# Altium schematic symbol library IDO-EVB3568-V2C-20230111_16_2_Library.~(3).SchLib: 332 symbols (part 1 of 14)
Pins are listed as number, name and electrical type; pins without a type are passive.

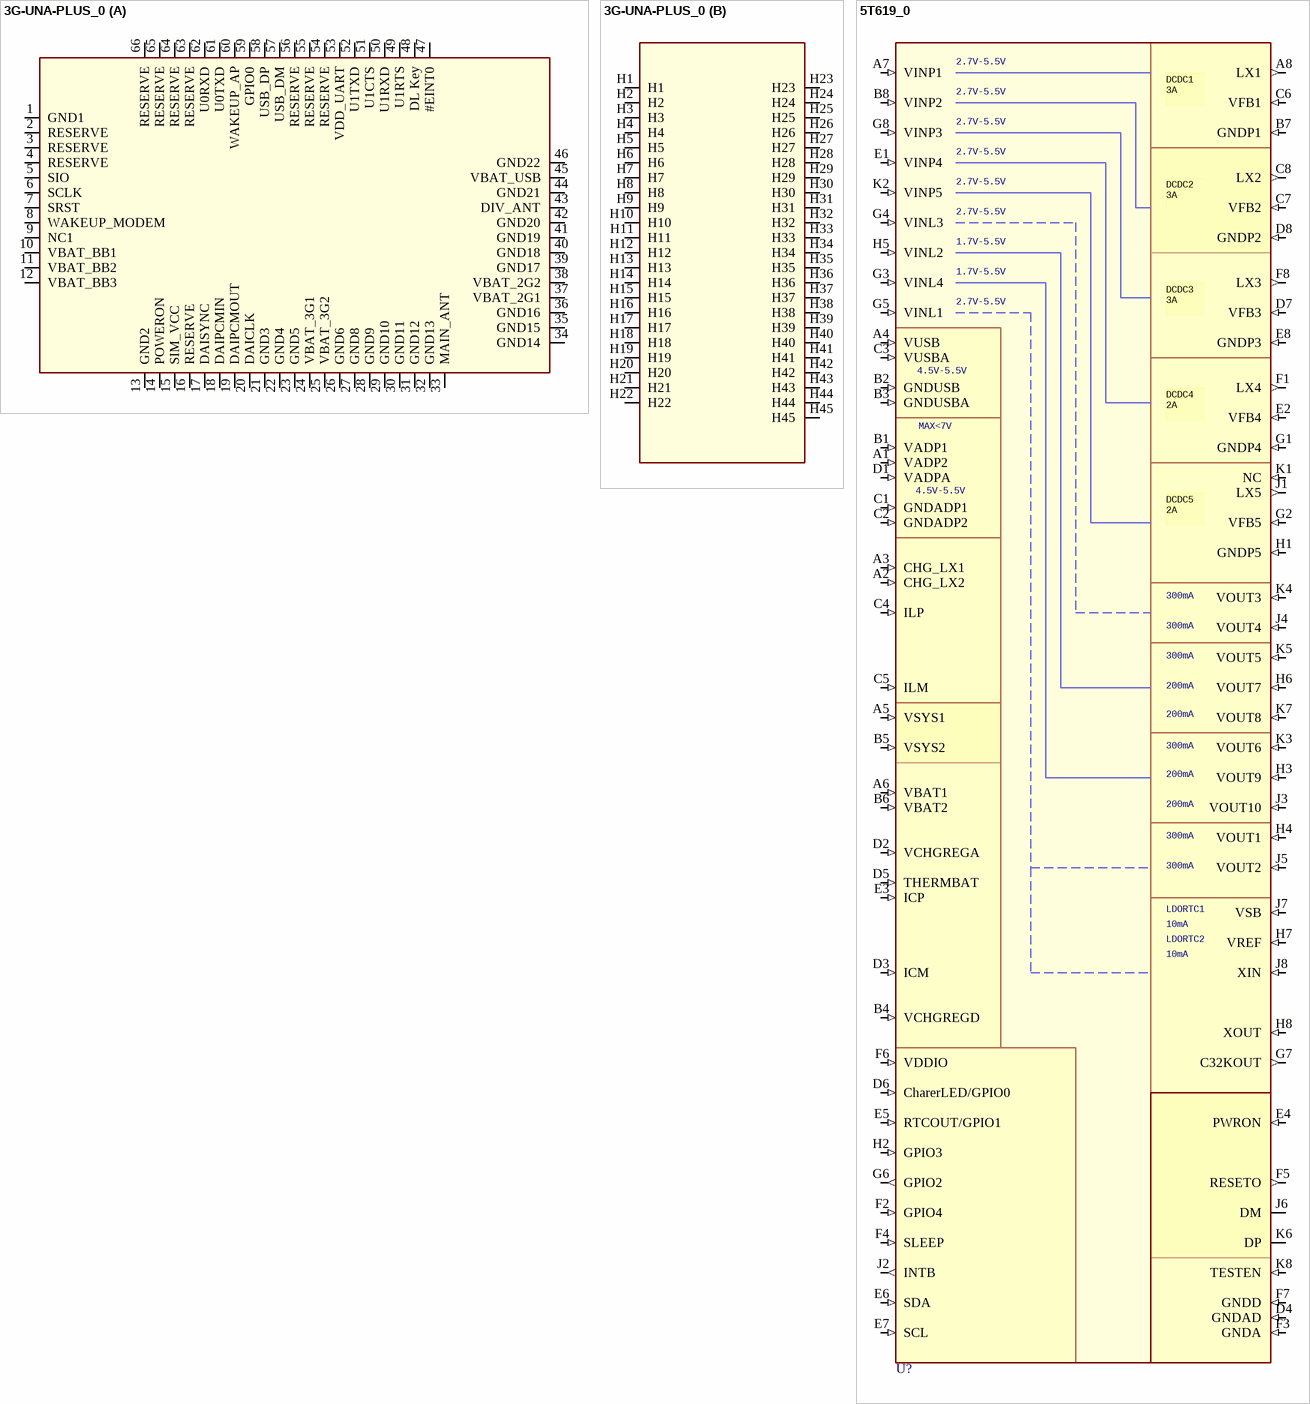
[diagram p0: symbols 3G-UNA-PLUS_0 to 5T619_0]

## 3G-UNA-PLUS_0
designator U?
Altium-Right: 340; Altium-Bottom: 210; Altium-Right1: 110; Altium-Bottom1: 280
part A pins: 1 GND1, 2 RESERVE, 3 RESERVE, 4 RESERVE, 5 SIO, 6 SCLK, 7 SRST, 8 WAKEUP_MODEM, 9 NC1, 10 VBAT_BB1, 11 VBAT_BB2, 12 VBAT_BB3, 13 GND2, 14 POWERON, 15 SIM_VCC, 16 RESERVE, 17 DAISYNC, 18 DAIPCMIN, 19 DAIPCMOUT, 20 DAICLK, 21 GND3, 22 GND4, 23 GND5, 24 VBAT_3G1, 25 VBAT_3G2, 26 GND6, 27 GND8, 28 GND9, 29 GND10, 30 GND11, 31 GND12, 32 GND13, 33 MAIN_ANT, 34 GND14, 35 GND15, 36 GND16, 37 VBAT_2G1, 38 VBAT_2G2, 39 GND17, 40 GND18, 41 GND19, 42 GND20, 43 DIV_ANT, 44 GND21, 45 VBAT_USB, 46 GND22, 47 #EINT0, 48 DL Key, 49 U1RTS, 50 U1RXD, 51 U1CTS, 52 U1TXD, 53 VDD_UART, 54 RESERVE, 55 RESERVE, 56 RESERVE, 57 USB_DM, 58 USB_DP, 59 GPIO0, 60 WAKEUP_AP, 61 U0TXD, 62 U0RXD, 63 RESERVE, 64 RESERVE, 65 RESERVE, 66 RESERVE
part B pins: H1, H2, H3, H4, H5, H6, H7, H8, H9, H10, H11, H12, H13, H14, H15, H16, H17, H18, H19, H20, H21, H22, H23, H24, H25, H26, H27, H28, H29, H30, H31, H32, H33, H34, H35, H36, H37, H38, H39, H40, H41, H42, H43, H44, H45

## 5T619_0
designator U?  (value not drawn)
Altium-Right: 250; Altium-Bottom: 880
pins: A1 VADP2 (in), A2 CHG_LX2 (in), A3 CHG_LX1 (in), A4 VUSB (in), A5 VSYS1 (in), A6 VBAT1 (in), A7 VINP1 (in), A8 LX1 (out), B1 VADP1 (in), B2 GNDUSB (in), B3 GNDUSBA (in), B4 VCHGREGD (in), B5 VSYS2 (in), B6 VBAT2 (in), B7 GNDP1 (in), B8 VINP2 (in), C1 GNDADP1 (in), C2 GNDADP2 (in), C3 VUSBA (in), C4 ILP (in), C5 ILM (in), C6 VFB1 (in), C7 VFB2 (in), C8 LX2 (out), D1 VADPA (in), D2 VCHGREGA (in), D3 ICM (in), D4 GNDAD (in), D5 THERMBAT (in), D6 CharerLED/GPIO0 (in), D7 VFB3 (in), D8 GNDP2 (in), E1 VINP4 (in), E2 VFB4 (in), E3 ICP (in), E4 PWRON (in), E5 RTCOUT/GPIO1 (in), E6 SDA (in), E7 SCL (in), E8 GNDP3 (in), F1 LX4 (out), F2 GPIO4 (in), F3 GNDA (in), F4 SLEEP (in), F5 RESETO (out), F6 VDDIO (in), F7 GNDD (in), F8 LX3 (out), G1 GNDP4 (in), G2 VFB5 (in), G3 VINL4 (in), G4 VINL3 (in), G5 VINL1 (in), G6 GPIO2 (out), G7 C32KOUT (out), G8 VINP3 (in), H1 GNDP5 (in), H2 GPIO3 (in), H3 VOUT9 (in), H4 VOUT1 (in), H5 VINL2 (in), H6 VOUT7 (in), H7 VREF (in), H8 XOUT (in), J1 LX5 (out), J2 INTB (out), J3 VOUT10 (in), J4 VOUT4 (in), J5 VOUT2 (in), J6 DM, J7 VSB (in), J8 XIN (in), K1 NC (in), K2 VINP5 (in), K3 VOUT6 (in), K4 VOUT3 (in), K5 VOUT5 (in), K6 DP, K7 VOUT8 (in), K8 TESTEN (in)

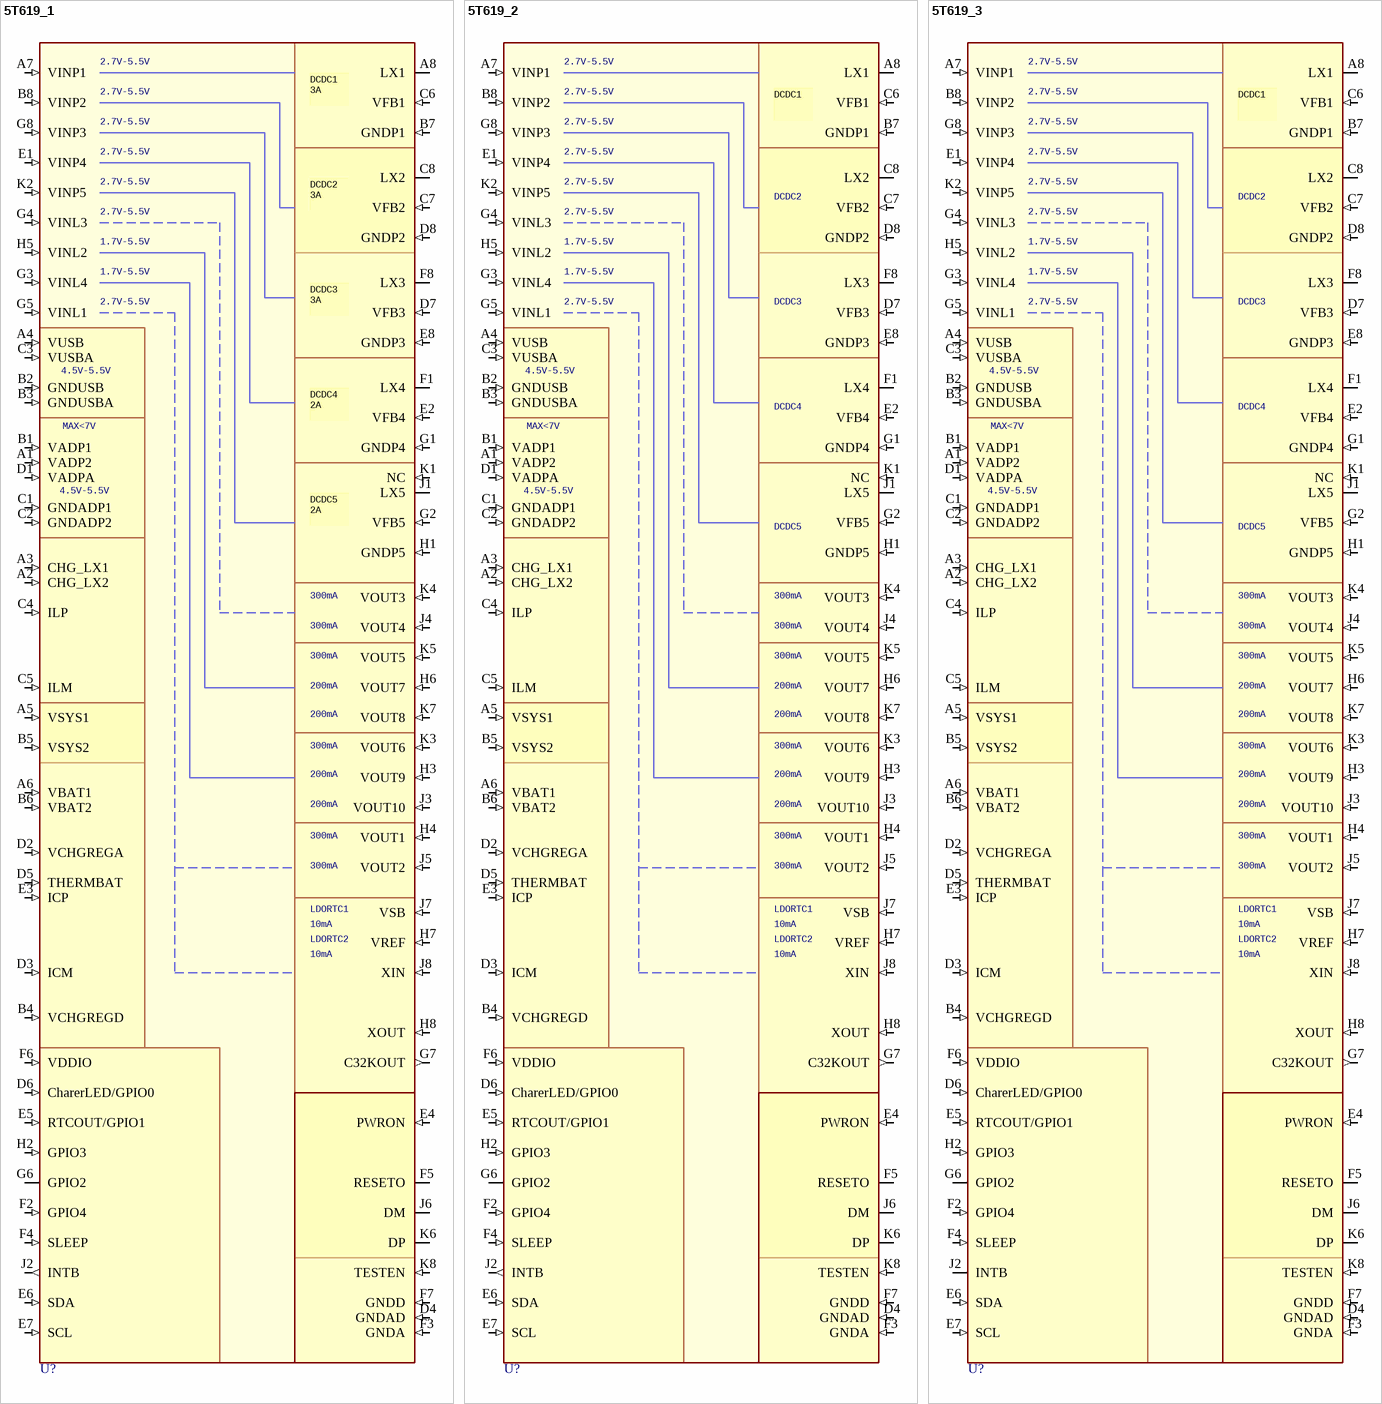
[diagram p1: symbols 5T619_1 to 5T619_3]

## 5T619_1
designator U?  (value not drawn)
Altium-Right: 250; Altium-Bottom: 880
pins: A1 VADP2 (in), A2 CHG_LX2 (in), A3 CHG_LX1 (in), A4 VUSB (in), A5 VSYS1 (in), A6 VBAT1 (in), A7 VINP1 (in), A8 LX1, B1 VADP1 (in), B2 GNDUSB (in), B3 GNDUSBA (in), B4 VCHGREGD (in), B5 VSYS2 (in), B6 VBAT2 (in), B7 GNDP1 (in), B8 VINP2 (in), C1 GNDADP1 (in), C2 GNDADP2 (in), C3 VUSBA (in), C4 ILP (in), C5 ILM (in), C6 VFB1 (in), C7 VFB2 (in), C8 LX2, D1 VADPA (in), D2 VCHGREGA (in), D3 ICM (in), D4 GNDAD (in), D5 THERMBAT (in), D6 CharerLED/GPIO0 (in), D7 VFB3 (in), D8 GNDP2 (in), E1 VINP4 (in), E2 VFB4 (in), E3 ICP (in), E4 PWRON (in), E5 RTCOUT/GPIO1 (in), E6 SDA (in), E7 SCL (in), E8 GNDP3 (in), F1 LX4, F2 GPIO4 (in), F3 GNDA (in), F4 SLEEP (in), F5 RESETO, F6 VDDIO (in), F7 GNDD (in), F8 LX3, G1 GNDP4 (in), G2 VFB5 (in), G3 VINL4 (in), G4 VINL3 (in), G5 VINL1 (in), G6 GPIO2, G7 C32KOUT (out), G8 VINP3 (in), H1 GNDP5 (in), H2 GPIO3 (in), H3 VOUT9 (in), H4 VOUT1 (in), H5 VINL2 (in), H6 VOUT7 (in), H7 VREF (in), H8 XOUT (in), J1 LX5, J2 INTB (out), J3 VOUT10 (in), J4 VOUT4 (in), J5 VOUT2 (in), J6 DM, J7 VSB (in), J8 XIN (in), K1 NC (in), K2 VINP5 (in), K3 VOUT6 (in), K4 VOUT3 (in), K5 VOUT5 (in), K6 DP, K7 VOUT8 (in), K8 TESTEN (in)

## 5T619_2
designator U?  (value not drawn)
Altium-Right: 250; Altium-Bottom: 880
pins: A1 VADP2 (in), A2 CHG_LX2 (in), A3 CHG_LX1 (in), A4 VUSB (in), A5 VSYS1 (in), A6 VBAT1 (in), A7 VINP1 (in), A8 LX1, B1 VADP1 (in), B2 GNDUSB (in), B3 GNDUSBA (in), B4 VCHGREGD (in), B5 VSYS2 (in), B6 VBAT2 (in), B7 GNDP1 (in), B8 VINP2 (in), C1 GNDADP1 (in), C2 GNDADP2 (in), C3 VUSBA (in), C4 ILP (in), C5 ILM (in), C6 VFB1 (in), C7 VFB2 (in), C8 LX2, D1 VADPA (in), D2 VCHGREGA (in), D3 ICM (in), D4 GNDAD (in), D5 THERMBAT (in), D6 CharerLED/GPIO0 (in), D7 VFB3 (in), D8 GNDP2 (in), E1 VINP4 (in), E2 VFB4 (in), E3 ICP (in), E4 PWRON (in), E5 RTCOUT/GPIO1 (in), E6 SDA (in), E7 SCL (in), E8 GNDP3 (in), F1 LX4, F2 GPIO4 (in), F3 GNDA (in), F4 SLEEP (in), F5 RESETO, F6 VDDIO (in), F7 GNDD (in), F8 LX3, G1 GNDP4 (in), G2 VFB5 (in), G3 VINL4 (in), G4 VINL3 (in), G5 VINL1 (in), G6 GPIO2, G7 C32KOUT (out), G8 VINP3 (in), H1 GNDP5 (in), H2 GPIO3 (in), H3 VOUT9 (in), H4 VOUT1 (in), H5 VINL2 (in), H6 VOUT7 (in), H7 VREF (in), H8 XOUT (in), J1 LX5, J2 INTB (out), J3 VOUT10 (in), J4 VOUT4 (in), J5 VOUT2 (in), J6 DM, J7 VSB (in), J8 XIN (in), K1 NC (in), K2 VINP5 (in), K3 VOUT6 (in), K4 VOUT3 (in), K5 VOUT5 (in), K6 DP, K7 VOUT8 (in), K8 TESTEN (in)

## 5T619_3
designator U?  (value not drawn)
Altium-Right: 250; Altium-Bottom: 880
pins: A1 VADP2 (in), A2 CHG_LX2 (in), A3 CHG_LX1 (in), A4 VUSB (in), A5 VSYS1 (in), A6 VBAT1 (in), A7 VINP1 (in), A8 LX1, B1 VADP1 (in), B2 GNDUSB (in), B3 GNDUSBA (in), B4 VCHGREGD (in), B5 VSYS2 (in), B6 VBAT2 (in), B7 GNDP1 (in), B8 VINP2 (in), C1 GNDADP1 (in), C2 GNDADP2 (in), C3 VUSBA (in), C4 ILP (in), C5 ILM (in), C6 VFB1 (in), C7 VFB2 (in), C8 LX2, D1 VADPA (in), D2 VCHGREGA (in), D3 ICM (in), D4 GNDAD (in), D5 THERMBAT (in), D6 CharerLED/GPIO0 (in), D7 VFB3 (in), D8 GNDP2 (in), E1 VINP4 (in), E2 VFB4 (in), E3 ICP (in), E4 PWRON (in), E5 RTCOUT/GPIO1 (in), E6 SDA (in), E7 SCL (in), E8 GNDP3 (in), F1 LX4, F2 GPIO4 (in), F3 GNDA (in), F4 SLEEP (in), F5 RESETO, F6 VDDIO (in), F7 GNDD (in), F8 LX3, G1 GNDP4 (in), G2 VFB5 (in), G3 VINL4 (in), G4 VINL3 (in), G5 VINL1 (in), G6 GPIO2, G7 C32KOUT (out), G8 VINP3 (in), H1 GNDP5 (in), H2 GPIO3 (in), H3 VOUT9 (in), H4 VOUT1 (in), H5 VINL2 (in), H6 VOUT7 (in), H7 VREF (in), H8 XOUT (in), J1 LX5, J2 INTB, J3 VOUT10 (in), J4 VOUT4 (in), J5 VOUT2 (in), J6 DM, J7 VSB (in), J8 XIN (in), K1 NC (in), K2 VINP5 (in), K3 VOUT6 (in), K4 VOUT3 (in), K5 VOUT5 (in), K6 DP, K7 VOUT8 (in), K8 TESTEN (in)

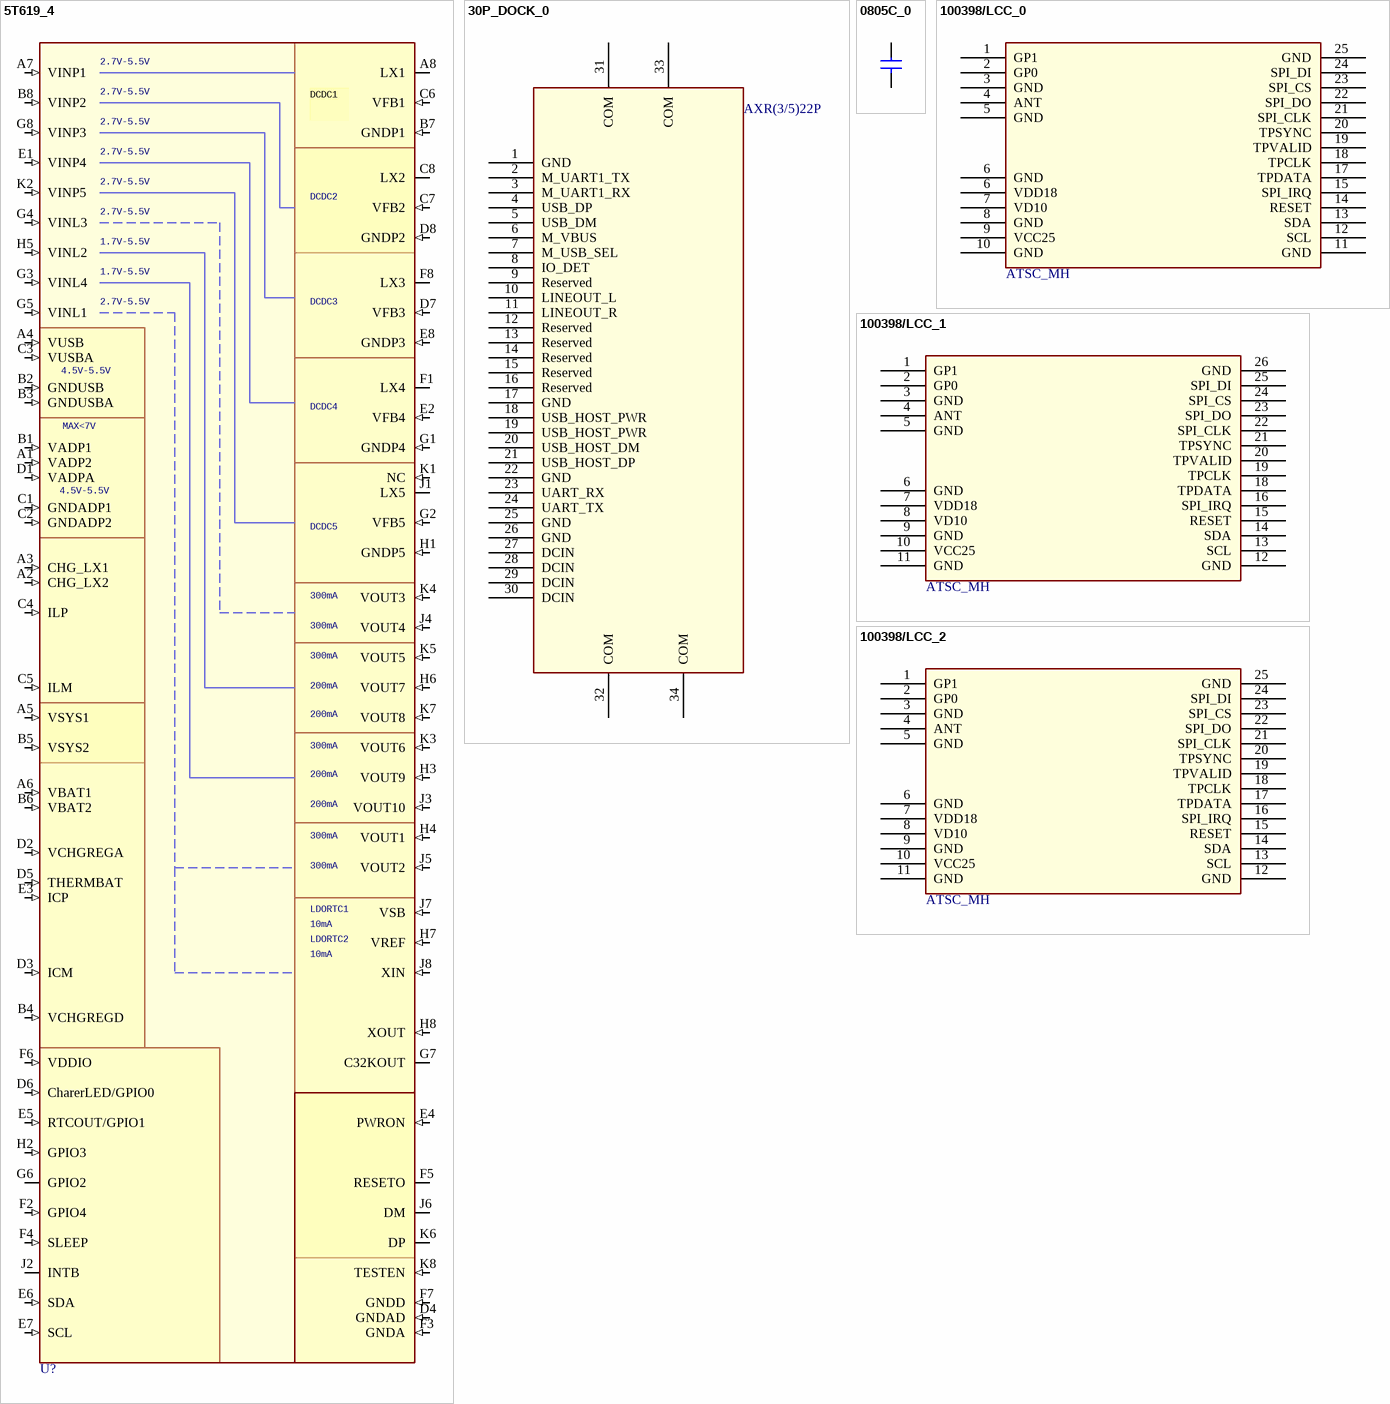
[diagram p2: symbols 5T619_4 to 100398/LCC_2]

## 5T619_4
designator U?  (value not drawn)
Altium-Right: 250; Altium-Bottom: 880
pins: A1 VADP2 (in), A2 CHG_LX2 (in), A3 CHG_LX1 (in), A4 VUSB (in), A5 VSYS1 (in), A6 VBAT1 (in), A7 VINP1 (in), A8 LX1, B1 VADP1 (in), B2 GNDUSB (in), B3 GNDUSBA (in), B4 VCHGREGD (in), B5 VSYS2 (in), B6 VBAT2 (in), B7 GNDP1 (in), B8 VINP2 (in), C1 GNDADP1 (in), C2 GNDADP2 (in), C3 VUSBA (in), C4 ILP (in), C5 ILM (in), C6 VFB1 (in), C7 VFB2 (in), C8 LX2, D1 VADPA (in), D2 VCHGREGA (in), D3 ICM (in), D4 GNDAD (in), D5 THERMBAT (in), D6 CharerLED/GPIO0 (in), D7 VFB3 (in), D8 GNDP2 (in), E1 VINP4 (in), E2 VFB4 (in), E3 ICP (in), E4 PWRON (in), E5 RTCOUT/GPIO1 (in), E6 SDA (in), E7 SCL (in), E8 GNDP3 (in), F1 LX4, F2 GPIO4 (in), F3 GNDA (in), F4 SLEEP (in), F5 RESETO, F6 VDDIO (in), F7 GNDD (in), F8 LX3, G1 GNDP4 (in), G2 VFB5 (in), G3 VINL4 (in), G4 VINL3 (in), G5 VINL1 (in), G6 GPIO2, G7 C32KOUT, G8 VINP3 (in), H1 GNDP5 (in), H2 GPIO3 (in), H3 VOUT9 (in), H4 VOUT1 (in), H5 VINL2 (in), H6 VOUT7 (in), H7 VREF (in), H8 XOUT (in), J1 LX5, J2 INTB, J3 VOUT10 (in), J4 VOUT4 (in), J5 VOUT2 (in), J6 DM, J7 VSB (in), J8 XIN (in), K1 NC (in), K2 VINP5 (in), K3 VOUT6 (in), K4 VOUT3 (in), K5 VOUT5 (in), K6 DP, K7 VOUT8 (in), K8 TESTEN (in)

## 30P_DOCK_0
designator CON?, comment AXR(3/5)22P
Altium-Right: 140; Altium-Bottom: 390
footprint 30P_DOCK_1
pins: 1 GND, 2 M_UART1_TX, 3 M_UART1_RX, 4 USB_DP, 5 USB_DM, 6 M_VBUS, 7 M_USB_SEL, 8 IO_DET, 9 Reserved, 10 LINEOUT_L, 11 LINEOUT_R, 12 Reserved, 13 Reserved, 14 Reserved, 15 Reserved, 16 Reserved, 17 GND, 18 USB_HOST_PWR, 19 USB_HOST_PWR, 20 USB_HOST_DM, 21 USB_HOST_DP, 22 GND, 23 UART_RX, 24 UART_TX, 25 GND, 26 GND, 27 DCIN, 28 DCIN, 29 DCIN, 30 DCIN, 31 COM, 32 COM, 33 COM, 34 COM

## 0805C_0
designator C?
Altium-Right: 20; Altium-Bottom: 10
footprint 0805C
pins: 1, 2

## 100398/LCC_0
designator U?, comment ATSC_MH
Altium-Right: 210; Altium-Bottom: 150
pins: 1 GP1, 2 GP0, 3 GND, 4 ANT, 5 GND, 6 VDD18, 6 GND, 7 VD10, 8 GND, 9 VCC25, 10 GND, 11 GND, 12 SCL, 13 SDA, 14 RESET, 15 SPI_IRQ, 17 TPDATA, 18 TPCLK, 19 TPVALID, 20 TPSYNC, 21 SPI_CLK, 22 SPI_DO, 23 SPI_CS, 24 SPI_DI, 25 GND

## 100398/LCC_1
designator U?, comment ATSC_MH
Altium-Right: 210; Altium-Bottom: 150
pins: 1 GP1, 2 GP0, 3 GND, 4 ANT, 5 GND, 6 GND, 7 VDD18, 8 VD10, 9 GND, 10 VCC25, 11 GND, 12 GND, 13 SCL, 14 SDA, 15 RESET, 16 SPI_IRQ, 18 TPDATA, 19 TPCLK, 20 TPVALID, 21 TPSYNC, 22 SPI_CLK, 23 SPI_DO, 24 SPI_CS, 25 SPI_DI, 26 GND

## 100398/LCC_2
designator U?, comment ATSC_MH
Altium-Right: 210; Altium-Bottom: 150
pins: 1 GP1, 2 GP0, 3 GND, 4 ANT, 5 GND, 6 GND, 7 VDD18, 8 VD10, 9 GND, 10 VCC25, 11 GND, 12 GND, 13 SCL, 14 SDA, 15 RESET, 16 SPI_IRQ, 17 TPDATA, 18 TPCLK, 19 TPVALID, 20 TPSYNC, 21 SPI_CLK, 22 SPI_DO, 23 SPI_CS, 24 SPI_DI, 25 GND

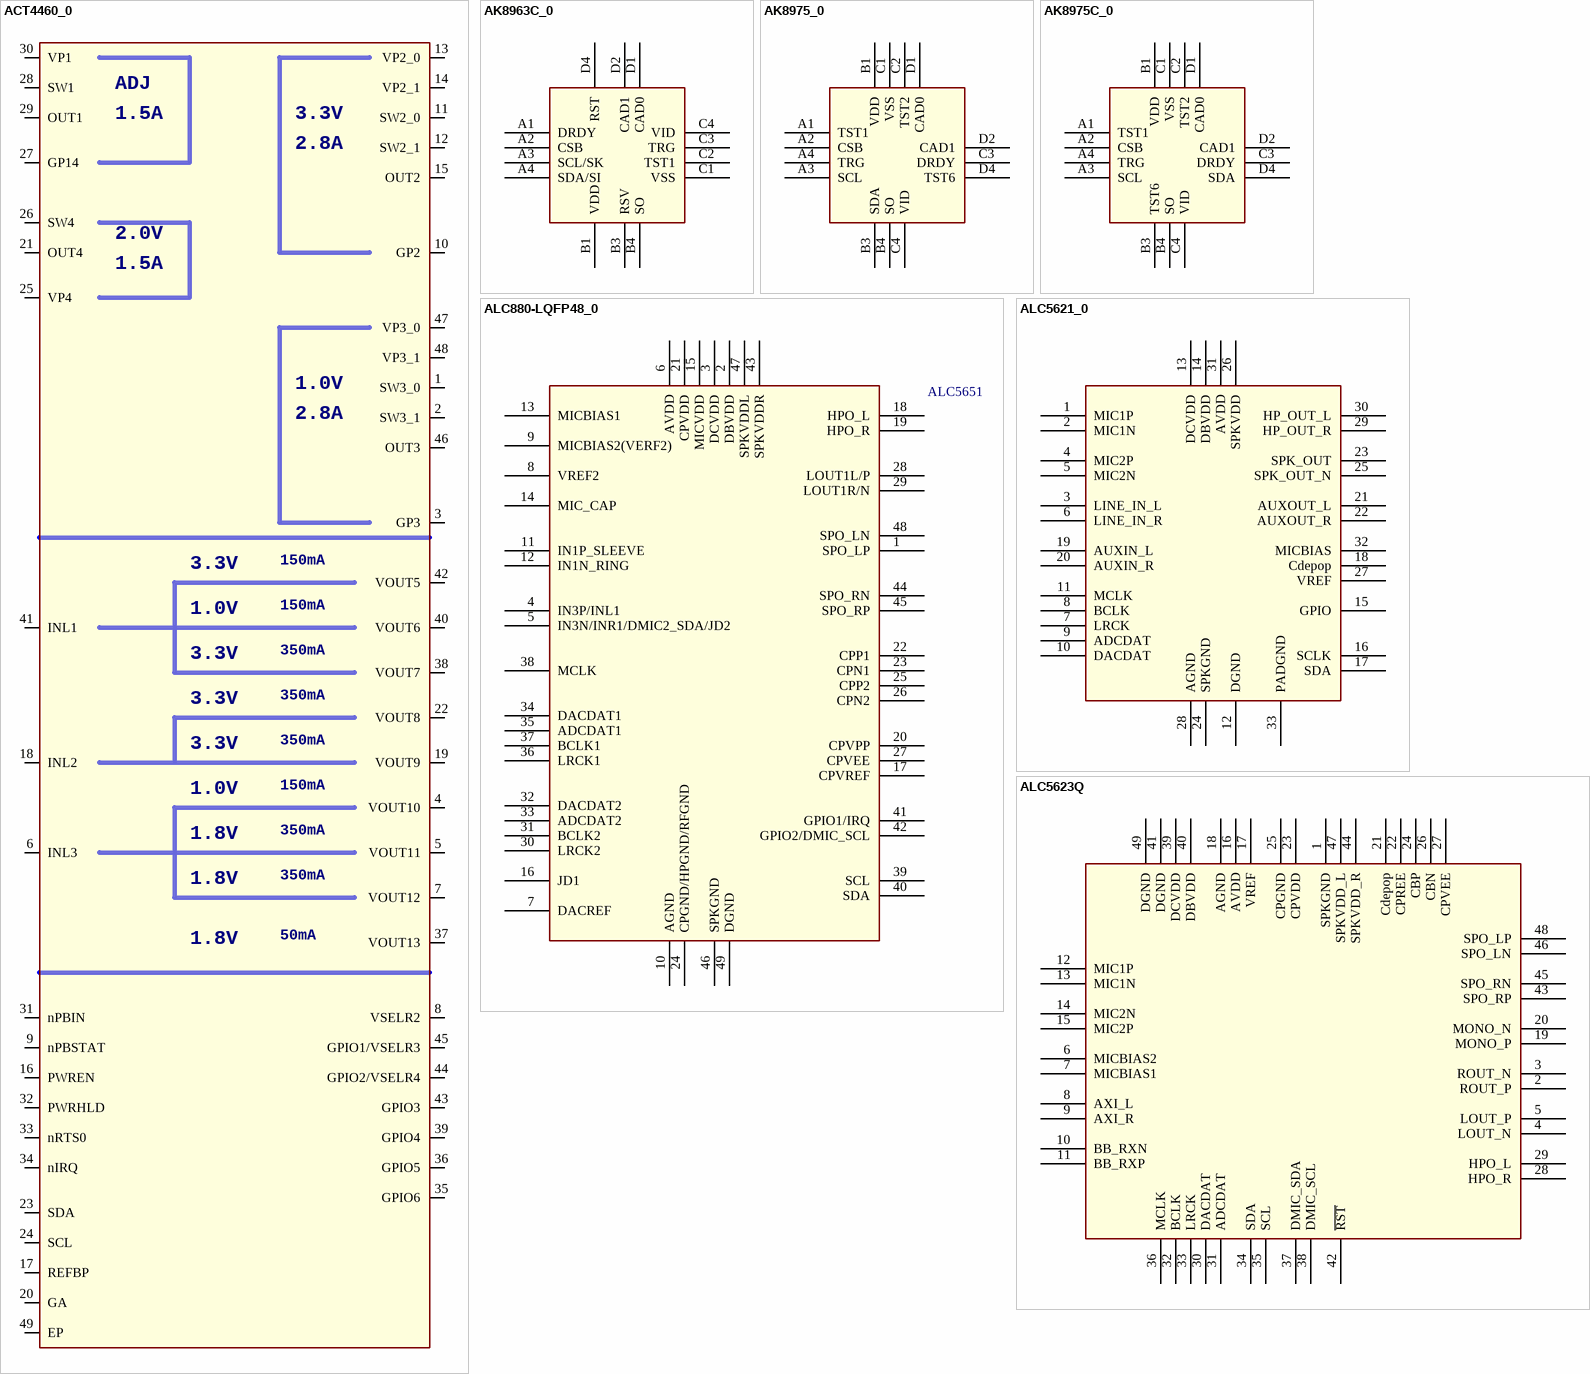
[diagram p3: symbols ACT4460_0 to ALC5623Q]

## ACT4460_0
designator U?
Altium-Right: 260; Altium-Bottom: 870
pins: 1 SW3_0, 2 SW3_1, 3 GP3, 4 VOUT10, 5 VOUT11, 6 INL3, 7 VOUT12, 8 VSELR2, 9 nPBSTAT, 10 GP2, 11 SW2_0, 12 SW2_1, 13 VP2_0, 14 VP2_1, 15 OUT2, 16 PWREN, 17 REFBP, 18 INL2, 19 VOUT9, 20 GA, 21 OUT4, 22 VOUT8, 23 SDA, 24 SCL, 25 VP4, 26 SW4, 27 GP14, 28 SW1, 29 OUT1, 30 VP1, 31 nPBIN, 32 PWRHLD, 33 nRTS0, 34 nIRQ, 35 GPIO6, 36 GPIO5, 37 VOUT13, 38 VOUT7, 39 GPIO4, 40 VOUT6, 41 INL1, 42 VOUT5, 43 GPIO3, 44 GPIO2/VSELR4, 45 GPIO1/VSELR3, 46 OUT3, 47 VP3_0, 48 VP3_1, 49 EP

## AK8963C_0
designator U?
Altium-Right: 90
footprint AK8975B
pins: A1 DRDY, A2 CSB, A3 SCL/SK, A4 SDA/SI, B1 VDD, B3 RSV, B4 SO, C1 VSS, C2 TST1, C3 TRG, C4 VID, D1 CAD0, D2 CAD1, D4 RST

## AK8975_0
designator U?
Altium-Right: 90
footprint QFN16-4X4
pins: A1 TST1, A2 CSB, A3 SCL, A4 TRG, B1 VDD, B3 SDA, B4 SO, C1 VSS, C2 TST2, C3 DRDY, C4 VID, D1 CAD0, D2 CAD1, D4 TST6

## AK8975C_0
designator U?
Altium-Right: 90
footprint AK8975B
pins: A1 TST1, A2 CSB, A3 SCL, A4 TRG, B1 VDD, B3 TST6, B4 SO, C1 VSS, C2 TST2, C3 DRDY, C4 VID, D1 CAD0, D2 CAD1, D4 SDA

## ALC880-LQFP48_0
designator U?, comment ALC5651
Altium-Right: 220; Altium-Bottom: 370
pins: 1 SPO_LP, 2 DBVDD, 3 DCVDD, 4 IN3P/INL1, 5 IN3N/INR1/DMIC2_SDA/JD2, 6 AVDD, 7 DACREF, 8 VREF2, 9 MICBIAS2(VERF2), 10 AGND, 11 IN1P_SLEEVE, 12 IN1N_RING, 13 MICBIAS1, 14 MIC_CAP, 15 MICVDD, 16 JD1, 17 CPVREF, 18 HPO_L, 19 HPO_R, 20 CPVPP, 21 CPVDD, 22 CPP1, 23 CPN1, 24 CPGND/HPGND/RFGND, 25 CPP2, 26 CPN2, 27 CPVEE, 28 LOUT1L/P, 29 LOUT1R/N, 30 LRCK2, 31 BCLK2, 32 DACDAT2, 33 ADCDAT2, 34 DACDAT1, 35 ADCDAT1, 36 LRCK1, 37 BCLK1, 38 MCLK, 39 SCL, 40 SDA, 41 GPIO1/IRQ, 42 GPIO2/DMIC_SCL, 43 SPKVDDR, 44 SPO_RN, 45 SPO_RP, 46 SPKGND, 47 SPKVDDL, 48 SPO_LN, 49 DGND

## ALC5621_0
designator U?
Altium-Right: 170; Altium-Bottom: 210
footprint QFN32
pins: 1 MIC1P, 2 MIC1N, 3 LINE_IN_L, 4 MIC2P, 5 MIC2N, 6 LINE_IN_R, 7 LRCK, 8 BCLK, 9 ADCDAT, 10 DACDAT, 11 MCLK, 12 DGND, 13 DCVDD, 14 DBVDD, 15 GPIO, 16 SCLK, 17 SDA, 18 Cdepop, 19 AUXIN_L, 20 AUXIN_R, 21 AUXOUT_L, 22 AUXOUT_R, 23 SPK_OUT, 24 SPKGND, 25 SPK_OUT_N, 26 SPKVDD, 27 VREF, 28 AGND, 29 HP_OUT_R, 30 HP_OUT_L, 31 AVDD, 32 MICBIAS, 33 PADGND

## ALC5623Q
designator U?
Altium-Right: 290; Altium-Bottom: 250
footprint QFN48-6X6
pins: 1 SPKGND, 2 ROUT_P, 3 ROUT_N, 4 LOUT_N, 5 LOUT_P, 6 MICBIAS2, 7 MICBIAS1, 8 AXI_L, 9 AXI_R, 10 BB_RXN, 11 BB_RXP, 12 MIC1P, 13 MIC1N, 14 MIC2N, 15 MIC2P, 16 AVDD, 17 VREF, 18 AGND, 19 MONO_P, 20 MONO_N, 21 Cdepop, 22 CPREE, 23 CPVDD, 24 CBP, 25 CPGND, 26 CBN, 27 CPVEE, 28 HPO_R, 29 HPO_L, 30 DACDAT, 31 ADCDAT, 32 BCLK, 33 LRCK, 34 SDA, 35 SCL, 36 MCLK, 37 DMIC_SDA, 38 DMIC_SCL, 39 DCVDD, 40 DBVDD, 41 DGND, 42 ~{RST}, 43 SPO_RP, 44 SPKVDD_R, 45 SPO_RN, 46 SPO_LN, 47 SPKVDD_L, 48 SPO_LP, 49 DGND

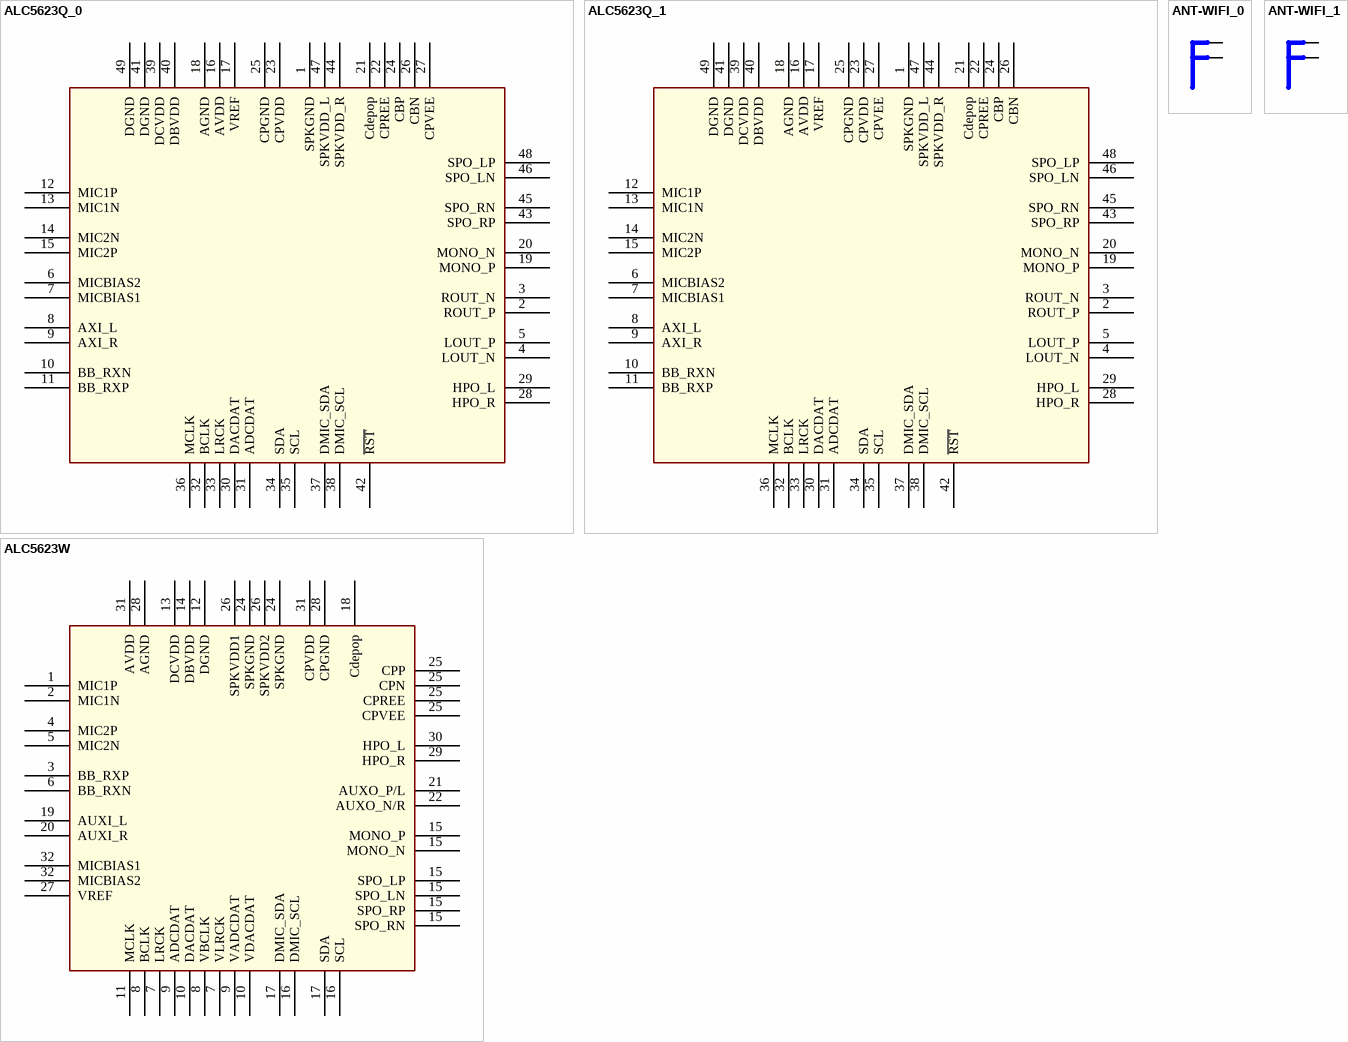
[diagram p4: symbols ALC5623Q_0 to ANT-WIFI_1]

## ALC5623Q_0
designator U?
Altium-Right: 290; Altium-Bottom: 250
footprint QFN48-6X6
pins: 1 SPKGND, 2 ROUT_P, 3 ROUT_N, 4 LOUT_N, 5 LOUT_P, 6 MICBIAS2, 7 MICBIAS1, 8 AXI_L, 9 AXI_R, 10 BB_RXN, 11 BB_RXP, 12 MIC1P, 13 MIC1N, 14 MIC2N, 15 MIC2P, 16 AVDD, 17 VREF, 18 AGND, 19 MONO_P, 20 MONO_N, 21 Cdepop, 22 CPREE, 23 CPVDD, 24 CBP, 25 CPGND, 26 CBN, 27 CPVEE, 28 HPO_R, 29 HPO_L, 30 DACDAT, 31 ADCDAT, 32 BCLK, 33 LRCK, 34 SDA, 35 SCL, 36 MCLK, 37 DMIC_SDA, 38 DMIC_SCL, 39 DCVDD, 40 DBVDD, 41 DGND, 42 ~{RST}, 43 SPO_RP, 44 SPKVDD_R, 45 SPO_RN, 46 SPO_LN, 47 SPKVDD_L, 48 SPO_LP, 49 DGND

## ALC5623Q_1
designator U?
Altium-Right: 290; Altium-Bottom: 250
footprint QFN48-6X6
pins: 1 SPKGND, 2 ROUT_P, 3 ROUT_N, 4 LOUT_N, 5 LOUT_P, 6 MICBIAS2, 7 MICBIAS1, 8 AXI_L, 9 AXI_R, 10 BB_RXN, 11 BB_RXP, 12 MIC1P, 13 MIC1N, 14 MIC2N, 15 MIC2P, 16 AVDD, 17 VREF, 18 AGND, 19 MONO_P, 20 MONO_N, 21 Cdepop, 22 CPREE, 23 CPVDD, 24 CBP, 25 CPGND, 26 CBN, 27 CPVEE, 28 HPO_R, 29 HPO_L, 30 DACDAT, 31 ADCDAT, 32 BCLK, 33 LRCK, 34 SDA, 35 SCL, 36 MCLK, 37 DMIC_SDA, 38 DMIC_SCL, 39 DCVDD, 40 DBVDD, 41 DGND, 42 ~{RST}, 43 SPO_RP, 44 SPKVDD_R, 45 SPO_RN, 46 SPO_LN, 47 SPKVDD_L, 48 SPO_LP, 49 DGND

## ALC5623W
designator U?
Altium-Right: 230
footprint GBA49
pins: 1 MIC1P, 2 MIC1N, 3 BB_RXP, 4 MIC2P, 5 MIC2N, 6 BB_RXN, 7 LRCK, 7 VLRCK, 8 BCLK, 8 VBCLK, 9 ADCDAT, 9 VADCDAT, 10 DACDAT, 10 VDACDAT, 11 MCLK, 12 DGND, 13 DCVDD, 14 DBVDD, 15 SPO_RN, 15 SPO_RP, 15 SPO_LP, 15 SPO_LN, 15 MONO_P, 15 MONO_N, 16 SCL, 16 DMIC_SCL, 17 SDA, 17 DMIC_SDA, 18 Cdepop, 19 AUXI_L, 20 AUXI_R, 21 AUXO_P/L, 22 AUXO_N/R, 24 SPKGND, 24 SPKGND, 25 CPVEE, 25 CPREE, 25 CPN, 25 CPP, 26 SPKVDD1, 26 SPKVDD2, 27 VREF, 28 AGND, 28 CPGND, 29 HPO_R, 30 HPO_L, 31 AVDD, 31 CPVDD, 32 MICBIAS1, 32 MICBIAS2

## ANT-WIFI_0
designator C?
Altium-Right: 20; Altium-Bottom: 32
pins: 1, 2

## ANT-WIFI_1
designator C?
Altium-Right: 20; Altium-Bottom: 32
pins: 1, 2

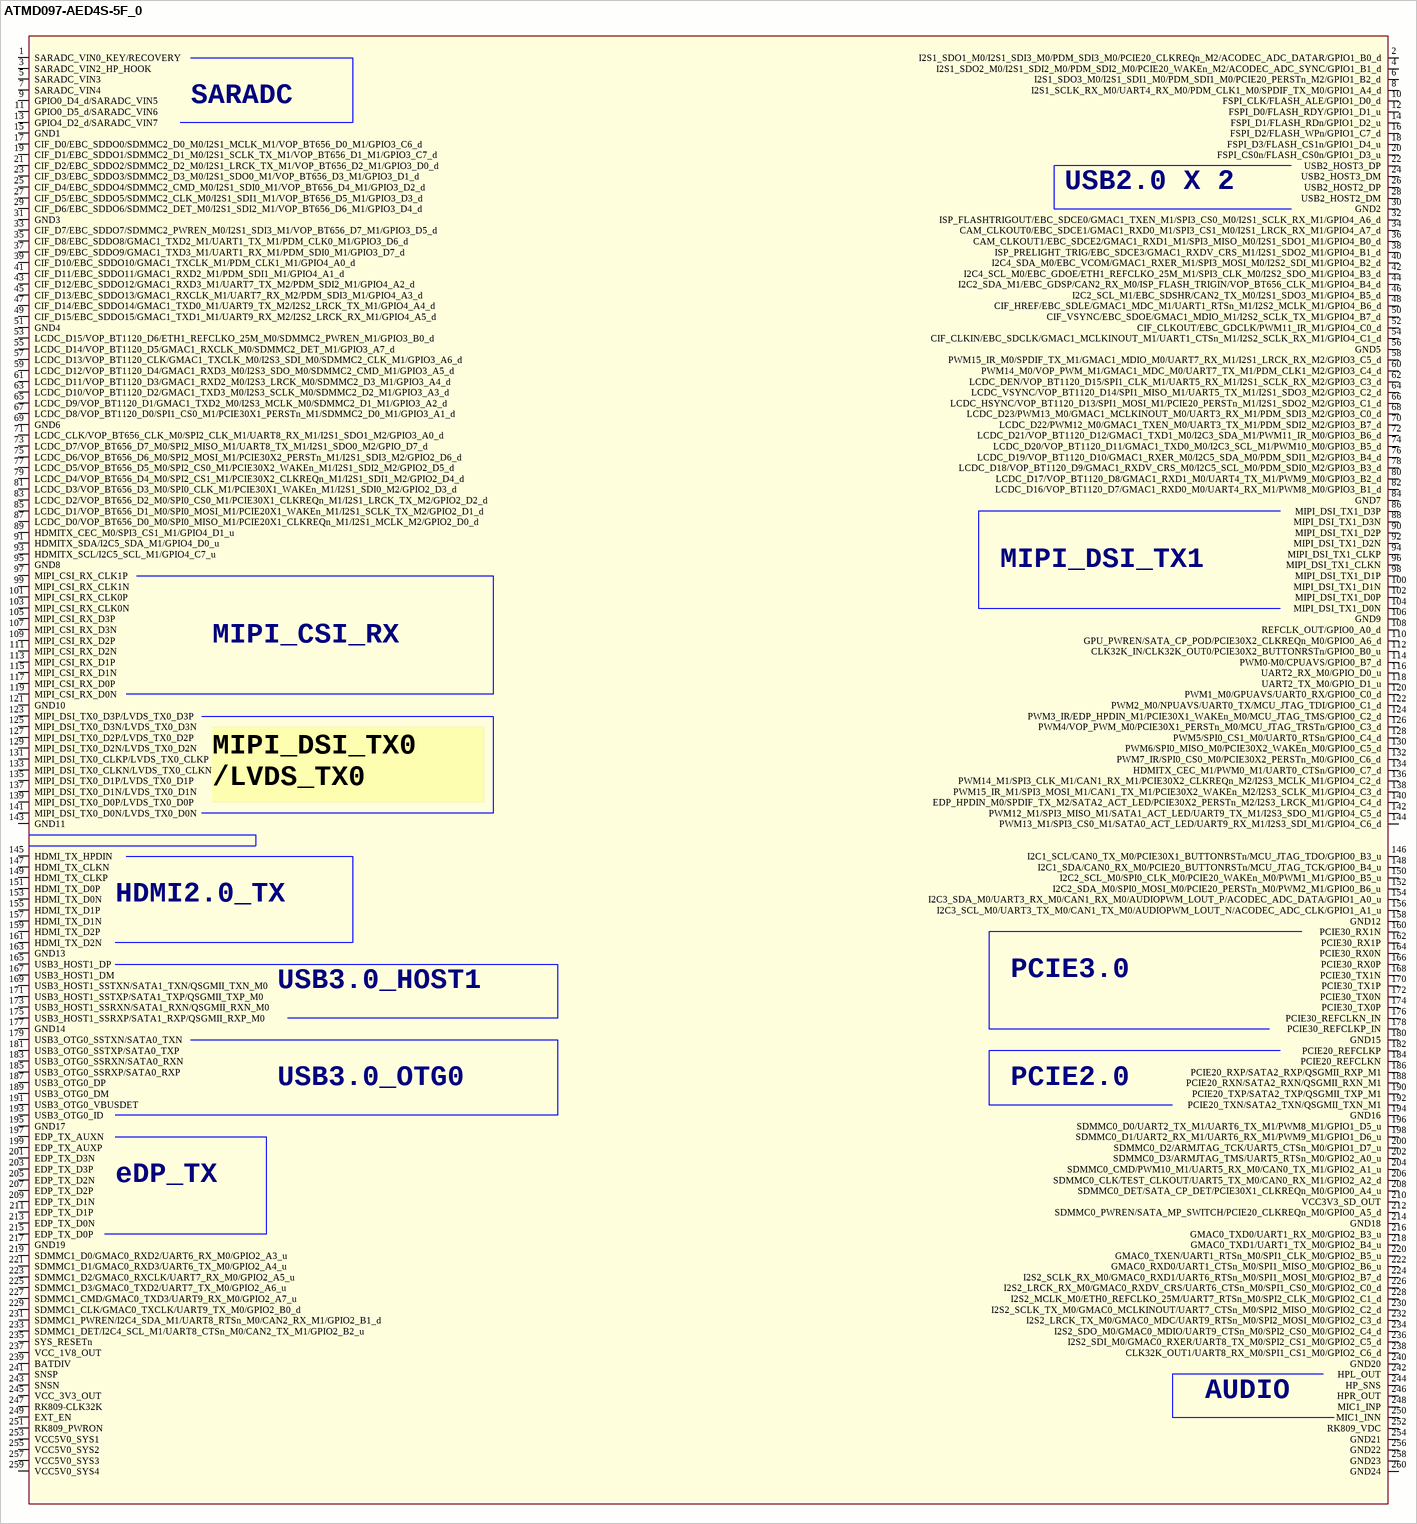
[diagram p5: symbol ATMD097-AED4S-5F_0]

## ATMD097-AED4S-5F_0
designator J?
Altium-Right: 1260; Altium-Bottom: 1360
pins: 1 SARADC_VIN0_KEY/RECOVERY, 2 I2S1_SDO1_M0/I2S1_SDI3_M0/PDM_SDI3_M0/PCIE20_CLKREQn_M2/ACODEC_ADC_DATAR/GPIO1_B0_d, 3 SARADC_VIN2_HP_HOOK, 4 I2S1_SDO2_M0/I2S1_SDI2_M0/PDM_SDI2_M0/PCIE20_WAKEn_M2/ACODEC_ADC_SYNC/GPIO1_B1_d, 5 SARADC_VIN3, 6 I2S1_SDO3_M0/I2S1_SDI1_M0/PDM_SDI1_M0/PCIE20_PERSTn_M2/GPIO1_B2_d, 7 SARADC_VIN4, 8 I2S1_SCLK_RX_M0/UART4_RX_M0/PDM_CLK1_M0/SPDIF_TX_M0/GPIO1_A4_d, 9 GPIO0_D4_d/SARADC_VIN5, 10 FSPI_CLK/FLASH_ALE/GPIO1_D0_d, 11 GPIO0_D5_d/SARADC_VIN6, 12 FSPI_D0/FLASH_RDY/GPIO1_D1_u, 13 GPIO4_D2_d/SARADC_VIN7, 14 FSPI_D1/FLASH_RDn/GPIO1_D2_u, 15 GND1, 16 FSPI_D2/FLASH_WPn/GPIO1_C7_d, 17 CIF_D0/EBC_SDDO0/SDMMC2_D0_M0/I2S1_MCLK_M1/VOP_BT656_D0_M1/GPIO3_C6_d, 18 FSPI_D3/FLASH_CS1n/GPIO1_D4_u, 19 CIF_D1/EBC_SDDO1/SDMMC2_D1_M0/I2S1_SCLK_TX_M1/VOP_BT656_D1_M1/GPIO3_C7_d, 20 FSPI_CS0n/FLASH_CS0n/GPIO1_D3_u, 21 CIF_D2/EBC_SDDO2/SDMMC2_D2_M0/I2S1_LRCK_TX_M1/VOP_BT656_D2_M1/GPIO3_D0_d, 22 USB2_HOST3_DP, 23 CIF_D3/EBC_SDDO3/SDMMC2_D3_M0/I2S1_SDO0_M1/VOP_BT656_D3_M1/GPIO3_D1_d, 24 USB2_HOST3_DM, 25 CIF_D4/EBC_SDDO4/SDMMC2_CMD_M0/I2S1_SDI0_M1/VOP_BT656_D4_M1/GPIO3_D2_d, 26 USB2_HOST2_DP, 27 CIF_D5/EBC_SDDO5/SDMMC2_CLK_M0/I2S1_SDI1_M1/VOP_BT656_D5_M1/GPIO3_D3_d, 28 USB2_HOST2_DM, 29 CIF_D6/EBC_SDDO6/SDMMC2_DET_M0/I2S1_SDI2_M1/VOP_BT656_D6_M1/GPIO3_D4_d, 30 GND2, 31 GND3, 32 ISP_FLASHTRIGOUT/EBC_SDCE0/GMAC1_TXEN_M1/SPI3_CS0_M0/I2S1_SCLK_RX_M1/GPIO4_A6_d, 33 CIF_D7/EBC_SDDO7/SDMMC2_PWREN_M0/I2S1_SDI3_M1/VOP_BT656_D7_M1/GPIO3_D5_d, 34 CAM_CLKOUT0/EBC_SDCE1/GMAC1_RXD0_M1/SPI3_CS1_M0/I2S1_LRCK_RX_M1/GPIO4_A7_d, 35 CIF_D8/EBC_SDDO8/GMAC1_TXD2_M1/UART1_TX_M1/PDM_CLK0_M1/GPIO3_D6_d, 36 CAM_CLKOUT1/EBC_SDCE2/GMAC1_RXD1_M1/SPI3_MISO_M0/I2S1_SDO1_M1/GPIO4_B0_d, 37 CIF_D9/EBC_SDDO9/GMAC1_TXD3_M1/UART1_RX_M1/PDM_SDI0_M1/GPIO3_D7_d, 38 ISP_PRELIGHT_TRIG/EBC_SDCE3/GMAC1_RXDV_CRS_M1/I2S1_SDO2_M1/GPIO4_B1_d, 39 CIF_D10/EBC_SDDO10/GMAC1_TXCLK_M1/PDM_CLK1_M1/GPIO4_A0_d, 40 I2C4_SDA_M0/EBC_VCOM/GMAC1_RXER_M1/SPI3_MOSI_M0/I2S2_SDI_M1/GPIO4_B2_d, 41 CIF_D11/EBC_SDDO11/GMAC1_RXD2_M1/PDM_SDI1_M1/GPIO4_A1_d, 42 I2C4_SCL_M0/EBC_GDOE/ETH1_REFCLKO_25M_M1/SPI3_CLK_M0/I2S2_SDO_M1/GPIO4_B3_d, 43 CIF_D12/EBC_SDDO12/GMAC1_RXD3_M1/UART7_TX_M2/PDM_SDI2_M1/GPIO4_A2_d, 44 I2C2_SDA_M1/EBC_GDSP/CAN2_RX_M0/ISP_FLASH_TRIGIN/VOP_BT656_CLK_M1/GPIO4_B4_d, 45 CIF_D13/EBC_SDDO13/GMAC1_RXCLK_M1/UART7_RX_M2/PDM_SDI3_M1/GPIO4_A3_d, 46 I2C2_SCL_M1/EBC_SDSHR/CAN2_TX_M0/I2S1_SDO3_M1/GPIO4_B5_d, 47 CIF_D14/EBC_SDDO14/GMAC1_TXD0_M1/UART9_TX_M2/I2S2_LRCK_TX_M1/GPIO4_A4_d, 48 CIF_HREF/EBC_SDLE/GMAC1_MDC_M1/UART1_RTSn_M1/I2S2_MCLK_M1/GPIO4_B6_d, 49 CIF_D15/EBC_SDDO15/GMAC1_TXD1_M1/UART9_RX_M2/I2S2_LRCK_RX_M1/GPIO4_A5_d, 50 CIF_VSYNC/EBC_SDOE/GMAC1_MDIO_M1/I2S2_SCLK_TX_M1/GPIO4_B7_d, 51 GND4, 52 CIF_CLKOUT/EBC_GDCLK/PWM11_IR_M1/GPIO4_C0_d, 53 LCDC_D15/VOP_BT1120_D6/ETH1_REFCLKO_25M_M0/SDMMC2_PWREN_M1/GPIO3_B0_d, 54 CIF_CLKIN/EBC_SDCLK/GMAC1_MCLKINOUT_M1/UART1_CTSn_M1/I2S2_SCLK_RX_M1/GPIO4_C1_d, 55 LCDC_D14/VOP_BT1120_D5/GMAC1_RXCLK_M0/SDMMC2_DET_M1/GPIO3_A7_d, 56 GND5, 57 LCDC_D13/VOP_BT1120_CLK/GMAC1_TXCLK_M0/I2S3_SDI_M0/SDMMC2_CLK_M1/GPIO3_A6_d, 58 PWM15_IR_M0/SPDIF_TX_M1/GMAC1_MDIO_M0/UART7_RX_M1/I2S1_LRCK_RX_M2/GPIO3_C5_d, 59 LCDC_D12/VOP_BT1120_D4/GMAC1_RXD3_M0/I2S3_SDO_M0/SDMMC2_CMD_M1/GPIO3_A5_d, 60 PWM14_M0/VOP_PWM_M1/GMAC1_MDC_M0/UART7_TX_M1/PDM_CLK1_M2/GPIO3_C4_d, 61 LCDC_D11/VOP_BT1120_D3/GMAC1_RXD2_M0/I2S3_LRCK_M0/SDMMC2_D3_M1/GPIO3_A4_d, 62 LCDC_DEN/VOP_BT1120_D15/SPI1_CLK_M1/UART5_RX_M1/I2S1_SCLK_RX_M2/GPIO3_C3_d, 63 LCDC_D10/VOP_BT1120_D2/GMAC1_TXD3_M0/I2S3_SCLK_M0/SDMMC2_D2_M1/GPIO3_A3_d, 64 LCDC_VSYNC/VOP_BT1120_D14/SPI1_MISO_M1/UART5_TX_M1/I2S1_SDO3_M2/GPIO3_C2_d, 65 LCDC_D9/VOP_BT1120_D1/GMAC1_TXD2_M0/I2S3_MCLK_M0/SDMMC2_D1_M1/GPIO3_A2_d, 66 LCDC_HSYNC/VOP_BT1120_D13/SPI1_MOSI_M1/PCIE20_PERSTn_M1/I2S1_SDO2_M2/GPIO3_C1_d, 67 LCDC_D8/VOP_BT1120_D0/SPI1_CS0_M1/PCIE30X1_PERSTn_M1/SDMMC2_D0_M1/GPIO3_A1_d, 68 LCDC_D23/PWM13_M0/GMAC1_MCLKINOUT_M0/UART3_RX_M1/PDM_SDI3_M2/GPIO3_C0_d, 69 GND6, 70 LCDC_D22/PWM12_M0/GMAC1_TXEN_M0/UART3_TX_M1/PDM_SDI2_M2/GPIO3_B7_d, 71 LCDC_CLK/VOP_BT656_CLK_M0/SPI2_CLK_M1/UART8_RX_M1/I2S1_SDO1_M2/GPIO3_A0_d, 72 LCDC_D21/VOP_BT1120_D12/GMAC1_TXD1_M0/I2C3_SDA_M1/PWM11_IR_M0/GPIO3_B6_d, 73 LCDC_D7/VOP_BT656_D7_M0/SPI2_MISO_M1/UART8_TX_M1/I2S1_SDO0_M2/GPIO_D7_d, 74 LCDC_D20/VOP_BT1120_D11/GMAC1_TXD0_M0/I2C3_SCL_M1/PWM10_M0/GPIO3_B5_d, 75 LCDC_D6/VOP_BT656_D6_M0/SPI2_MOSI_M1/PCIE30X2_PERSTn_M1/I2S1_SDI3_M2/GPIO2_D6_d, 76 LCDC_D19/VOP_BT1120_D10/GMAC1_RXER_M0/I2C5_SDA_M0/PDM_SDI1_M2/GPIO3_B4_d, 77 LCDC_D5/VOP_BT656_D5_M0/SPI2_CS0_M1/PCIE30X2_WAKEn_M1/I2S1_SDI2_M2/GPIO2_D5_d, 78 LCDC_D18/VOP_BT1120_D9/GMAC1_RXDV_CRS_M0/I2C5_SCL_M0/PDM_SDI0_M2/GPIO3_B3_d, 79 LCDC_D4/VOP_BT656_D4_M0/SPI2_CS1_M1/PCIE30X2_CLKREQn_M1/I2S1_SDI1_M2/GPIO2_D4_d, 80 LCDC_D17/VOP_BT1120_D8/GMAC1_RXD1_M0/UART4_TX_M1/PWM9_M0/GPIO3_B2_d, 81 LCDC_D3/VOP_BT656_D3_M0/SPI0_CLK_M1/PCIE30X1_WAKEn_M1/I2S1_SDI0_M2/GPIO2_D3_d, 82 LCDC_D16/VOP_BT1120_D7/GMAC1_RXD0_M0/UART4_RX_M1/PWM8_M0/GPIO3_B1_d, 83 LCDC_D2/VOP_BT656_D2_M0/SPI0_CS0_M1/PCIE30X1_CLKREQn_M1/I2S1_LRCK_TX_M2/GPIO2_D2_d, 84 GND7, 85 LCDC_D1/VOP_BT656_D1_M0/SPI0_MOSI_M1/PCIE20X1_WAKEn_M1/I2S1_SCLK_TX_M2/GPIO2_D1_d, 86 MIPI_DSI_TX1_D3P, 87 LCDC_D0/VOP_BT656_D0_M0/SPI0_MISO_M1/PCIE20X1_CLKREQn_M1/I2S1_MCLK_M2/GPIO2_D0_d, 88 MIPI_DSI_TX1_D3N, 89 HDMITX_CEC_M0/SPI3_CS1_M1/GPIO4_D1_u, 90 MIPI_DSI_TX1_D2P, 91 HDMITX_SDA/I2C5_SDA_M1/GPIO4_D0_u, 92 MIPI_DSI_TX1_D2N, 93 HDMITX_SCL/I2C5_SCL_M1/GPIO4_C7_u, 94 MIPI_DSI_TX1_CLKP, 95 GND8, 96 MIPI_DSI_TX1_CLKN, 97 MIPI_CSI_RX_CLK1P, 98 MIPI_DSI_TX1_D1P, 99 MIPI_CSI_RX_CLK1N, 100 MIPI_DSI_TX1_D1N, 101 MIPI_CSI_RX_CLK0P, 102 MIPI_DSI_TX1_D0P, 103 MIPI_CSI_RX_CLK0N, 104 MIPI_DSI_TX1_D0N, 105 MIPI_CSI_RX_D3P, 106 GND9, 107 MIPI_CSI_RX_D3N, 108 REFCLK_OUT/GPIO0_A0_d, 109 MIPI_CSI_RX_D2P, 110 GPU_PWREN/SATA_CP_POD/PCIE30X2_CLKREQn_M0/GPIO0_A6_d, 111 MIPI_CSI_RX_D2N, 112 CLK32K_IN/CLK32K_OUT0/PCIE30X2_BUTTONRSTn/GPIO0_B0_u, 113 MIPI_CSI_RX_D1P, 114 PWM0-M0/CPUAVS/GPIO0_B7_d, 115 MIPI_CSI_RX_D1N, 116 UART2_RX_M0/GPIO_D0_u, 117 MIPI_CSI_RX_D0P, 118 UART2_TX_M0/GPIO_D1_u, 119 MIPI_CSI_RX_D0N, 120 PWM1_M0/GPUAVS/UART0_RX/GPIO0_C0_d, 121 GND10, 122 PWM2_M0/NPUAVS/UART0_TX/MCU_JTAG_TDI/GPIO0_C1_d, 123 MIPI_DSI_TX0_D3P/LVDS_TX0_D3P, 124 PWM3_IR/EDP_HPDIN_M1/PCIE30X1_WAKEn_M0/MCU_JTAG_TMS/GPIO0_C2_d, 125 MIPI_DSI_TX0_D3N/LVDS_TX0_D3N, 126 PWM4/VOP_PWM_M0/PCIE30X1_PERSTn_M0/MCU_JTAG_TRSTn/GPIO0_C3_d, 127 MIPI_DSI_TX0_D2P/LVDS_TX0_D2P, 128 PWM5/SPI0_CS1_M0/UART0_RTSn/GPIO0_C4_d, 129 MIPI_DSI_TX0_D2N/LVDS_TX0_D2N, 130 PWM6/SPI0_MISO_M0/PCIE30X2_WAKEn_M0/GPIO0_C5_d, 131 MIPI_DSI_TX0_CLKP/LVDS_TX0_CLKP, 132 PWM7_IR/SPI0_CS0_M0/PCIE30X2_PERSTn_M0/GPIO0_C6_d, 133 MIPI_DSI_TX0_CLKN/LVDS_TX0_CLKN, 134 HDMITX_CEC_M1/PWM0_M1/UART0_CTSn/GPIO0_C7_d, 135 MIPI_DSI_TX0_D1P/LVDS_TX0_D1P, 136 PWM14_M1/SPI3_CLK_M1/CAN1_RX_M1/PCIE30X2_CLKREQn_M2/I2S3_MCLK_M1/GPIO4_C2_d, 137 MIPI_DSI_TX0_D1N/LVDS_TX0_D1N, 138 PWM15_IR_M1/SPI3_MOSI_M1/CAN1_TX_M1/PCIE30X2_WAKEn_M2/I2S3_SCLK_M1/GPIO4_C3_d, 139 MIPI_DSI_TX0_D0P/LVDS_TX0_D0P, 140 EDP_HPDIN_M0/SPDIF_TX_M2/SATA2_ACT_LED/PCIE30X2_PERSTn_M2/I2S3_LRCK_M1/GPIO4_C4_d, 141 MIPI_DSI_TX0_D0N/LVDS_TX0_D0N, 142 PWM12_M1/SPI3_MISO_M1/SATA1_ACT_LED/UART9_TX_M1/I2S3_SDO_M1/GPIO4_C5_d, 143 GND11, 144 PWM13_M1/SPI3_CS0_M1/SATA0_ACT_LED/UART9_RX_M1/I2S3_SDI_M1/GPIO4_C6_d, 145 HDMI_TX_HPDIN, 146 I2C1_SCL/CAN0_TX_M0/PCIE30X1_BUTTONRSTn/MCU_JTAG_TDO/GPIO0_B3_u, 147 HDMI_TX_CLKN, 148 I2C1_SDA/CAN0_RX_M0/PCIE20_BUTTONRSTn/MCU_JTAG_TCK/GPIO0_B4_u, 149 HDMI_TX_CLKP, 150 I2C2_SCL_M0/SPI0_CLK_M0/PCIE20_WAKEn_M0/PWM1_M1/GPIO0_B5_u, 151 HDMI_TX_D0P, 152 I2C2_SDA_M0/SPI0_MOSI_M0/PCIE20_PERSTn_M0/PWM2_M1/GPIO0_B6_u, 153 HDMI_TX_D0N, 154 I2C3_SDA_M0/UART3_RX_M0/CAN1_RX_M0/AUDIOPWM_LOUT_P/ACODEC_ADC_DATA/GPIO1_A0_u, 155 HDMI_TX_D1P, 156 I2C3_SCL_M0/UART3_TX_M0/CAN1_TX_M0/AUDIOPWM_LOUT_N/ACODEC_ADC_CLK/GPIO1_A1_u, 157 HDMI_TX_D1N, 158 GND12, 159 HDMI_TX_D2P, 160 PCIE30_RX1N, 161 HDMI_TX_D2N, 162 PCIE30_RX1P, 163 GND13, 164 PCIE30_RX0N, 165 USB3_HOST1_DP, 166 PCIE30_RX0P, 167 USB3_HOST1_DM, 168 PCIE30_TX1N, 169 USB3_HOST1_SSTXN/SATA1_TXN/QSGMII_TXN_M0, 170 PCIE30_TX1P, 171 USB3_HOST1_SSTXP/SATA1_TXP/QSGMII_TXP_M0, 172 PCIE30_TX0N, 173 USB3_HOST1_SSRXN/SATA1_RXN/QSGMII_RXN_M0, 174 PCIE30_TX0P, 175 USB3_HOST1_SSRXP/SATA1_RXP/QSGMII_RXP_M0, 176 PCIE30_REFCLKN_IN, 177 GND14, 178 PCIE30_REFCLKP_IN, 179 USB3_OTG0_SSTXN/SATA0_TXN, 180 GND15, 181 USB3_OTG0_SSTXP/SATA0_TXP, 182 PCIE20_REFCLKP, 183 USB3_OTG0_SSRXN/SATA0_RXN, 184 PCIE20_REFCLKN, 185 USB3_OTG0_SSRXP/SATA0_RXP, 186 PCIE20_RXP/SATA2_RXP/QSGMII_RXP_M1, 187 USB3_OTG0_DP, 188 PCIE20_RXN/SATA2_RXN/QSGMII_RXN_M1, 189 USB3_OTG0_DM, 190 PCIE20_TXP/SATA2_TXP/QSGMII_TXP_M1, 191 USB3_OTG0_VBUSDET, 192 PCIE20_TXN/SATA2_TXN/QSGMII_TXN_M1, 193 USB3_OTG0_ID, 194 GND16, 195 GND17, 196 SDMMC0_D0/UART2_TX_M1/UART6_TX_M1/PWM8_M1/GPIO1_D5_u, 197 EDP_TX_AUXN, 198 SDMMC0_D1/UART2_RX_M1/UART6_RX_M1/PWM9_M1/GPIO1_D6_u, 199 EDP_TX_AUXP, 200 SDMMC0_D2/ARMJTAG_TCK/UART5_CTSn_M0/GPIO1_D7_u, 201 EDP_TX_D3N, 202 SDMMC0_D3/ARMJTAG_TMS/UART5_RTSn_M0/GPIO2_A0_u, 203 EDP_TX_D3P, 204 SDMMC0_CMD/PWM10_M1/UART5_RX_M0/CAN0_TX_M1/GPIO2_A1_u, 205 EDP_TX_D2N, 206 SDMMC0_CLK/TEST_CLKOUT/UART5_TX_M0/CAN0_RX_M1/GPIO2_A2_d, 207 EDP_TX_D2P, 208 SDMMC0_DET/SATA_CP_DET/PCIE30X1_CLKREQn_M0/GPIO0_A4_u, 209 EDP_TX_D1N, 210 VCC3V3_SD_OUT, 211 EDP_TX_D1P, 212 SDMMC0_PWREN/SATA_MP_SWITCH/PCIE20_CLKREQn_M0/GPIO0_A5_d, 213 EDP_TX_D0N, 214 GND18, 215 EDP_TX_D0P, 216 GMAC0_TXD0/UART1_RX_M0/GPIO2_B3_u, 217 GND19, 218 GMAC0_TXD1/UART1_TX_M0/GPIO2_B4_u, 219 SDMMC1_D0/GMAC0_RXD2/UART6_RX_M0/GPIO2_A3_u, 220 GMAC0_TXEN/UART1_RTSn_M0/SPI1_CLK_M0/GPIO2_B5_u, 221 SDMMC1_D1/GMAC0_RXD3/UART6_TX_M0/GPIO2_A4_u, 222 GMAC0_RXD0/UART1_CTSn_M0/SPI1_MISO_M0/GPIO2_B6_u, 223 SDMMC1_D2/GMAC0_RXCLK/UART7_RX_M0/GPIO2_A5_u, 224 I2S2_SCLK_RX_M0/GMAC0_RXD1/UART6_RTSn_M0/SPI1_MOSI_M0/GPIO2_B7_d, 225 SDMMC1_D3/GMAC0_TXD2/UART7_TX_M0/GPIO2_A6_u, 226 I2S2_LRCK_RX_M0/GMAC0_RXDV_CRS/UART6_CTSn_M0/SPI1_CS0_M0/GPIO2_C0_d, 227 SDMMC1_CMD/GMAC0_TXD3/UART9_RX_M0/GPIO2_A7_u, 228 I2S2_MCLK_M0/ETH0_REFCLKO_25M/UART7_RTSn_M0/SPI2_CLK_M0/GPIO2_C1_d, 229 SDMMC1_CLK/GMAC0_TXCLK/UART9_TX_M0/GPIO2_B0_d, 230 I2S2_SCLK_TX_M0/GMAC0_MCLKINOUT/UART7_CTSn_M0/SPI2_MISO_M0/GPIO2_C2_d, 231 SDMMC1_PWREN/I2C4_SDA_M1/UART8_RTSn_M0/CAN2_RX_M1/GPIO2_B1_d, 232 I2S2_LRCK_TX_M0/GMAC0_MDC/UART9_RTSn_M0/SPI2_MOSI_M0/GPIO2_C3_d, 233 SDMMC1_DET/I2C4_SCL_M1/UART8_CTSn_M0/CAN2_TX_M1/GPIO2_B2_u, 234 I2S2_SDO_M0/GMAC0_MDIO/UART9_CTSn_M0/SPI2_CS0_M0/GPIO2_C4_d, 235 SYS_RESETn, 236 I2S2_SDI_M0/GMAC0_RXER/UART8_TX_M0/SPI2_CS1_M0/GPIO2_C5_d, 237 VCC_1V8_OUT, 238 CLK32K_OUT1/UART8_RX_M0/SPI1_CS1_M0/GPIO2_C6_d, 239 BATDIV, 240 GND20, 241 SNSP, 242 HPL_OUT, 243 SNSN, 244 HP_SNS, 245 VCC_3V3_OUT, 246 HPR_OUT, 247 RK809-CLK32K, 248 MIC1_INP, 249 EXT_EN, 250 MIC1_INN, 251 RK809_PWRON, 252 RK809_VDC, 253 VCC5V0_SYS1, 254 GND21, 255 VCC5V0_SYS2, 256 GND22, 257 VCC5V0_SYS3, 258 GND23, 259 VCC5V0_SYS4, 260 GND24

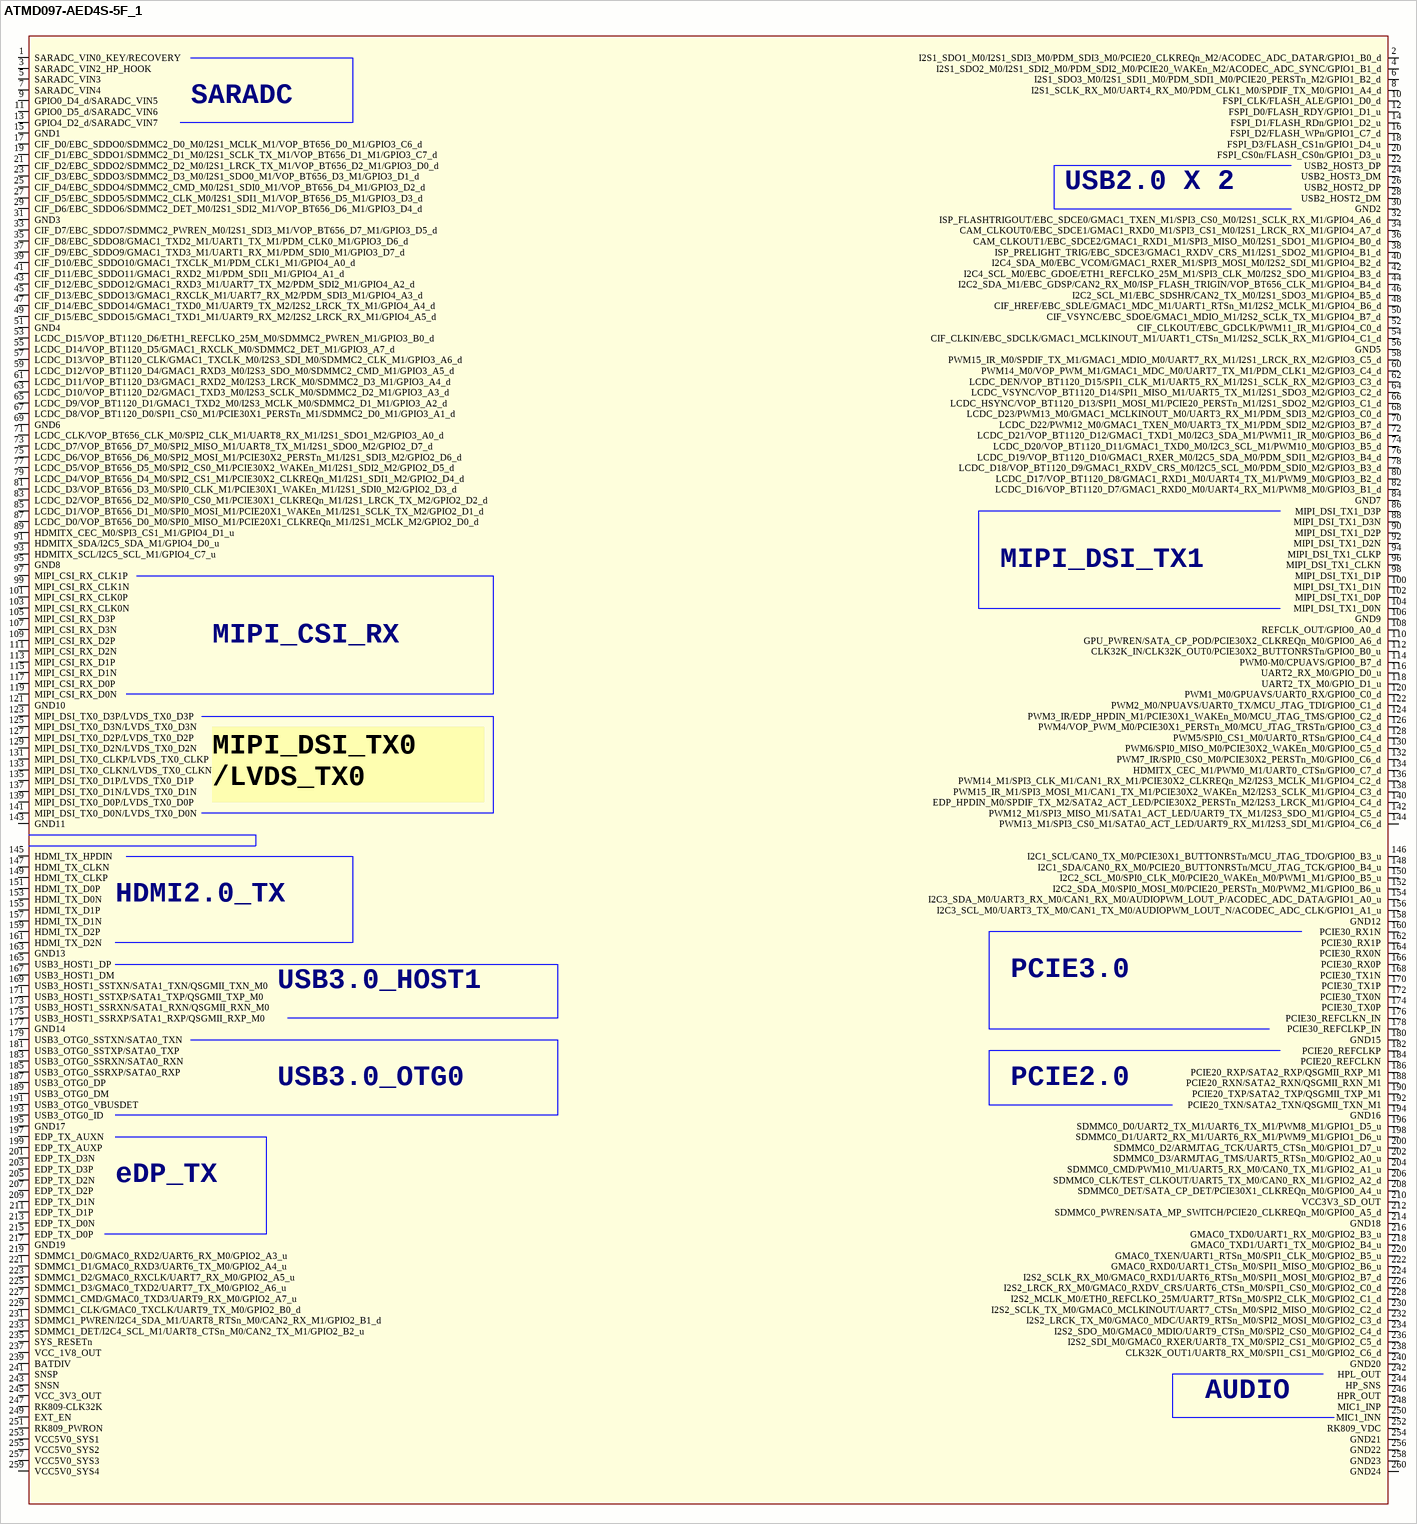
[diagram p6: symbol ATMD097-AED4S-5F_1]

## ATMD097-AED4S-5F_1
designator J?
Altium-Right: 1260; Altium-Bottom: 1360
pins: 1 SARADC_VIN0_KEY/RECOVERY, 2 I2S1_SDO1_M0/I2S1_SDI3_M0/PDM_SDI3_M0/PCIE20_CLKREQn_M2/ACODEC_ADC_DATAR/GPIO1_B0_d, 3 SARADC_VIN2_HP_HOOK, 4 I2S1_SDO2_M0/I2S1_SDI2_M0/PDM_SDI2_M0/PCIE20_WAKEn_M2/ACODEC_ADC_SYNC/GPIO1_B1_d, 5 SARADC_VIN3, 6 I2S1_SDO3_M0/I2S1_SDI1_M0/PDM_SDI1_M0/PCIE20_PERSTn_M2/GPIO1_B2_d, 7 SARADC_VIN4, 8 I2S1_SCLK_RX_M0/UART4_RX_M0/PDM_CLK1_M0/SPDIF_TX_M0/GPIO1_A4_d, 9 GPIO0_D4_d/SARADC_VIN5, 10 FSPI_CLK/FLASH_ALE/GPIO1_D0_d, 11 GPIO0_D5_d/SARADC_VIN6, 12 FSPI_D0/FLASH_RDY/GPIO1_D1_u, 13 GPIO4_D2_d/SARADC_VIN7, 14 FSPI_D1/FLASH_RDn/GPIO1_D2_u, 15 GND1, 16 FSPI_D2/FLASH_WPn/GPIO1_C7_d, 17 CIF_D0/EBC_SDDO0/SDMMC2_D0_M0/I2S1_MCLK_M1/VOP_BT656_D0_M1/GPIO3_C6_d, 18 FSPI_D3/FLASH_CS1n/GPIO1_D4_u, 19 CIF_D1/EBC_SDDO1/SDMMC2_D1_M0/I2S1_SCLK_TX_M1/VOP_BT656_D1_M1/GPIO3_C7_d, 20 FSPI_CS0n/FLASH_CS0n/GPIO1_D3_u, 21 CIF_D2/EBC_SDDO2/SDMMC2_D2_M0/I2S1_LRCK_TX_M1/VOP_BT656_D2_M1/GPIO3_D0_d, 22 USB2_HOST3_DP, 23 CIF_D3/EBC_SDDO3/SDMMC2_D3_M0/I2S1_SDO0_M1/VOP_BT656_D3_M1/GPIO3_D1_d, 24 USB2_HOST3_DM, 25 CIF_D4/EBC_SDDO4/SDMMC2_CMD_M0/I2S1_SDI0_M1/VOP_BT656_D4_M1/GPIO3_D2_d, 26 USB2_HOST2_DP, 27 CIF_D5/EBC_SDDO5/SDMMC2_CLK_M0/I2S1_SDI1_M1/VOP_BT656_D5_M1/GPIO3_D3_d, 28 USB2_HOST2_DM, 29 CIF_D6/EBC_SDDO6/SDMMC2_DET_M0/I2S1_SDI2_M1/VOP_BT656_D6_M1/GPIO3_D4_d, 30 GND2, 31 GND3, 32 ISP_FLASHTRIGOUT/EBC_SDCE0/GMAC1_TXEN_M1/SPI3_CS0_M0/I2S1_SCLK_RX_M1/GPIO4_A6_d, 33 CIF_D7/EBC_SDDO7/SDMMC2_PWREN_M0/I2S1_SDI3_M1/VOP_BT656_D7_M1/GPIO3_D5_d, 34 CAM_CLKOUT0/EBC_SDCE1/GMAC1_RXD0_M1/SPI3_CS1_M0/I2S1_LRCK_RX_M1/GPIO4_A7_d, 35 CIF_D8/EBC_SDDO8/GMAC1_TXD2_M1/UART1_TX_M1/PDM_CLK0_M1/GPIO3_D6_d, 36 CAM_CLKOUT1/EBC_SDCE2/GMAC1_RXD1_M1/SPI3_MISO_M0/I2S1_SDO1_M1/GPIO4_B0_d, 37 CIF_D9/EBC_SDDO9/GMAC1_TXD3_M1/UART1_RX_M1/PDM_SDI0_M1/GPIO3_D7_d, 38 ISP_PRELIGHT_TRIG/EBC_SDCE3/GMAC1_RXDV_CRS_M1/I2S1_SDO2_M1/GPIO4_B1_d, 39 CIF_D10/EBC_SDDO10/GMAC1_TXCLK_M1/PDM_CLK1_M1/GPIO4_A0_d, 40 I2C4_SDA_M0/EBC_VCOM/GMAC1_RXER_M1/SPI3_MOSI_M0/I2S2_SDI_M1/GPIO4_B2_d, 41 CIF_D11/EBC_SDDO11/GMAC1_RXD2_M1/PDM_SDI1_M1/GPIO4_A1_d, 42 I2C4_SCL_M0/EBC_GDOE/ETH1_REFCLKO_25M_M1/SPI3_CLK_M0/I2S2_SDO_M1/GPIO4_B3_d, 43 CIF_D12/EBC_SDDO12/GMAC1_RXD3_M1/UART7_TX_M2/PDM_SDI2_M1/GPIO4_A2_d, 44 I2C2_SDA_M1/EBC_GDSP/CAN2_RX_M0/ISP_FLASH_TRIGIN/VOP_BT656_CLK_M1/GPIO4_B4_d, 45 CIF_D13/EBC_SDDO13/GMAC1_RXCLK_M1/UART7_RX_M2/PDM_SDI3_M1/GPIO4_A3_d, 46 I2C2_SCL_M1/EBC_SDSHR/CAN2_TX_M0/I2S1_SDO3_M1/GPIO4_B5_d, 47 CIF_D14/EBC_SDDO14/GMAC1_TXD0_M1/UART9_TX_M2/I2S2_LRCK_TX_M1/GPIO4_A4_d, 48 CIF_HREF/EBC_SDLE/GMAC1_MDC_M1/UART1_RTSn_M1/I2S2_MCLK_M1/GPIO4_B6_d, 49 CIF_D15/EBC_SDDO15/GMAC1_TXD1_M1/UART9_RX_M2/I2S2_LRCK_RX_M1/GPIO4_A5_d, 50 CIF_VSYNC/EBC_SDOE/GMAC1_MDIO_M1/I2S2_SCLK_TX_M1/GPIO4_B7_d, 51 GND4, 52 CIF_CLKOUT/EBC_GDCLK/PWM11_IR_M1/GPIO4_C0_d, 53 LCDC_D15/VOP_BT1120_D6/ETH1_REFCLKO_25M_M0/SDMMC2_PWREN_M1/GPIO3_B0_d, 54 CIF_CLKIN/EBC_SDCLK/GMAC1_MCLKINOUT_M1/UART1_CTSn_M1/I2S2_SCLK_RX_M1/GPIO4_C1_d, 55 LCDC_D14/VOP_BT1120_D5/GMAC1_RXCLK_M0/SDMMC2_DET_M1/GPIO3_A7_d, 56 GND5, 57 LCDC_D13/VOP_BT1120_CLK/GMAC1_TXCLK_M0/I2S3_SDI_M0/SDMMC2_CLK_M1/GPIO3_A6_d, 58 PWM15_IR_M0/SPDIF_TX_M1/GMAC1_MDIO_M0/UART7_RX_M1/I2S1_LRCK_RX_M2/GPIO3_C5_d, 59 LCDC_D12/VOP_BT1120_D4/GMAC1_RXD3_M0/I2S3_SDO_M0/SDMMC2_CMD_M1/GPIO3_A5_d, 60 PWM14_M0/VOP_PWM_M1/GMAC1_MDC_M0/UART7_TX_M1/PDM_CLK1_M2/GPIO3_C4_d, 61 LCDC_D11/VOP_BT1120_D3/GMAC1_RXD2_M0/I2S3_LRCK_M0/SDMMC2_D3_M1/GPIO3_A4_d, 62 LCDC_DEN/VOP_BT1120_D15/SPI1_CLK_M1/UART5_RX_M1/I2S1_SCLK_RX_M2/GPIO3_C3_d, 63 LCDC_D10/VOP_BT1120_D2/GMAC1_TXD3_M0/I2S3_SCLK_M0/SDMMC2_D2_M1/GPIO3_A3_d, 64 LCDC_VSYNC/VOP_BT1120_D14/SPI1_MISO_M1/UART5_TX_M1/I2S1_SDO3_M2/GPIO3_C2_d, 65 LCDC_D9/VOP_BT1120_D1/GMAC1_TXD2_M0/I2S3_MCLK_M0/SDMMC2_D1_M1/GPIO3_A2_d, 66 LCDC_HSYNC/VOP_BT1120_D13/SPI1_MOSI_M1/PCIE20_PERSTn_M1/I2S1_SDO2_M2/GPIO3_C1_d, 67 LCDC_D8/VOP_BT1120_D0/SPI1_CS0_M1/PCIE30X1_PERSTn_M1/SDMMC2_D0_M1/GPIO3_A1_d, 68 LCDC_D23/PWM13_M0/GMAC1_MCLKINOUT_M0/UART3_RX_M1/PDM_SDI3_M2/GPIO3_C0_d, 69 GND6, 70 LCDC_D22/PWM12_M0/GMAC1_TXEN_M0/UART3_TX_M1/PDM_SDI2_M2/GPIO3_B7_d, 71 LCDC_CLK/VOP_BT656_CLK_M0/SPI2_CLK_M1/UART8_RX_M1/I2S1_SDO1_M2/GPIO3_A0_d, 72 LCDC_D21/VOP_BT1120_D12/GMAC1_TXD1_M0/I2C3_SDA_M1/PWM11_IR_M0/GPIO3_B6_d, 73 LCDC_D7/VOP_BT656_D7_M0/SPI2_MISO_M1/UART8_TX_M1/I2S1_SDO0_M2/GPIO2_D7_d, 74 LCDC_D20/VOP_BT1120_D11/GMAC1_TXD0_M0/I2C3_SCL_M1/PWM10_M0/GPIO3_B5_d, 75 LCDC_D6/VOP_BT656_D6_M0/SPI2_MOSI_M1/PCIE30X2_PERSTn_M1/I2S1_SDI3_M2/GPIO2_D6_d, 76 LCDC_D19/VOP_BT1120_D10/GMAC1_RXER_M0/I2C5_SDA_M0/PDM_SDI1_M2/GPIO3_B4_d, 77 LCDC_D5/VOP_BT656_D5_M0/SPI2_CS0_M1/PCIE30X2_WAKEn_M1/I2S1_SDI2_M2/GPIO2_D5_d, 78 LCDC_D18/VOP_BT1120_D9/GMAC1_RXDV_CRS_M0/I2C5_SCL_M0/PDM_SDI0_M2/GPIO3_B3_d, 79 LCDC_D4/VOP_BT656_D4_M0/SPI2_CS1_M1/PCIE30X2_CLKREQn_M1/I2S1_SDI1_M2/GPIO2_D4_d, 80 LCDC_D17/VOP_BT1120_D8/GMAC1_RXD1_M0/UART4_TX_M1/PWM9_M0/GPIO3_B2_d, 81 LCDC_D3/VOP_BT656_D3_M0/SPI0_CLK_M1/PCIE30X1_WAKEn_M1/I2S1_SDI0_M2/GPIO2_D3_d, 82 LCDC_D16/VOP_BT1120_D7/GMAC1_RXD0_M0/UART4_RX_M1/PWM8_M0/GPIO3_B1_d, 83 LCDC_D2/VOP_BT656_D2_M0/SPI0_CS0_M1/PCIE30X1_CLKREQn_M1/I2S1_LRCK_TX_M2/GPIO2_D2_d, 84 GND7, 85 LCDC_D1/VOP_BT656_D1_M0/SPI0_MOSI_M1/PCIE20X1_WAKEn_M1/I2S1_SCLK_TX_M2/GPIO2_D1_d, 86 MIPI_DSI_TX1_D3P, 87 LCDC_D0/VOP_BT656_D0_M0/SPI0_MISO_M1/PCIE20X1_CLKREQn_M1/I2S1_MCLK_M2/GPIO2_D0_d, 88 MIPI_DSI_TX1_D3N, 89 HDMITX_CEC_M0/SPI3_CS1_M1/GPIO4_D1_u, 90 MIPI_DSI_TX1_D2P, 91 HDMITX_SDA/I2C5_SDA_M1/GPIO4_D0_u, 92 MIPI_DSI_TX1_D2N, 93 HDMITX_SCL/I2C5_SCL_M1/GPIO4_C7_u, 94 MIPI_DSI_TX1_CLKP, 95 GND8, 96 MIPI_DSI_TX1_CLKN, 97 MIPI_CSI_RX_CLK1P, 98 MIPI_DSI_TX1_D1P, 99 MIPI_CSI_RX_CLK1N, 100 MIPI_DSI_TX1_D1N, 101 MIPI_CSI_RX_CLK0P, 102 MIPI_DSI_TX1_D0P, 103 MIPI_CSI_RX_CLK0N, 104 MIPI_DSI_TX1_D0N, 105 MIPI_CSI_RX_D3P, 106 GND9, 107 MIPI_CSI_RX_D3N, 108 REFCLK_OUT/GPIO0_A0_d, 109 MIPI_CSI_RX_D2P, 110 GPU_PWREN/SATA_CP_POD/PCIE30X2_CLKREQn_M0/GPIO0_A6_d, 111 MIPI_CSI_RX_D2N, 112 CLK32K_IN/CLK32K_OUT0/PCIE30X2_BUTTONRSTn/GPIO0_B0_u, 113 MIPI_CSI_RX_D1P, 114 PWM0-M0/CPUAVS/GPIO0_B7_d, 115 MIPI_CSI_RX_D1N, 116 UART2_RX_M0/GPIO_D0_u, 117 MIPI_CSI_RX_D0P, 118 UART2_TX_M0/GPIO_D1_u, 119 MIPI_CSI_RX_D0N, 120 PWM1_M0/GPUAVS/UART0_RX/GPIO0_C0_d, 121 GND10, 122 PWM2_M0/NPUAVS/UART0_TX/MCU_JTAG_TDI/GPIO0_C1_d, 123 MIPI_DSI_TX0_D3P/LVDS_TX0_D3P, 124 PWM3_IR/EDP_HPDIN_M1/PCIE30X1_WAKEn_M0/MCU_JTAG_TMS/GPIO0_C2_d, 125 MIPI_DSI_TX0_D3N/LVDS_TX0_D3N, 126 PWM4/VOP_PWM_M0/PCIE30X1_PERSTn_M0/MCU_JTAG_TRSTn/GPIO0_C3_d, 127 MIPI_DSI_TX0_D2P/LVDS_TX0_D2P, 128 PWM5/SPI0_CS1_M0/UART0_RTSn/GPIO0_C4_d, 129 MIPI_DSI_TX0_D2N/LVDS_TX0_D2N, 130 PWM6/SPI0_MISO_M0/PCIE30X2_WAKEn_M0/GPIO0_C5_d, 131 MIPI_DSI_TX0_CLKP/LVDS_TX0_CLKP, 132 PWM7_IR/SPI0_CS0_M0/PCIE30X2_PERSTn_M0/GPIO0_C6_d, 133 MIPI_DSI_TX0_CLKN/LVDS_TX0_CLKN, 134 HDMITX_CEC_M1/PWM0_M1/UART0_CTSn/GPIO0_C7_d, 135 MIPI_DSI_TX0_D1P/LVDS_TX0_D1P, 136 PWM14_M1/SPI3_CLK_M1/CAN1_RX_M1/PCIE30X2_CLKREQn_M2/I2S3_MCLK_M1/GPIO4_C2_d, 137 MIPI_DSI_TX0_D1N/LVDS_TX0_D1N, 138 PWM15_IR_M1/SPI3_MOSI_M1/CAN1_TX_M1/PCIE30X2_WAKEn_M2/I2S3_SCLK_M1/GPIO4_C3_d, 139 MIPI_DSI_TX0_D0P/LVDS_TX0_D0P, 140 EDP_HPDIN_M0/SPDIF_TX_M2/SATA2_ACT_LED/PCIE30X2_PERSTn_M2/I2S3_LRCK_M1/GPIO4_C4_d, 141 MIPI_DSI_TX0_D0N/LVDS_TX0_D0N, 142 PWM12_M1/SPI3_MISO_M1/SATA1_ACT_LED/UART9_TX_M1/I2S3_SDO_M1/GPIO4_C5_d, 143 GND11, 144 PWM13_M1/SPI3_CS0_M1/SATA0_ACT_LED/UART9_RX_M1/I2S3_SDI_M1/GPIO4_C6_d, 145 HDMI_TX_HPDIN, 146 I2C1_SCL/CAN0_TX_M0/PCIE30X1_BUTTONRSTn/MCU_JTAG_TDO/GPIO0_B3_u, 147 HDMI_TX_CLKN, 148 I2C1_SDA/CAN0_RX_M0/PCIE20_BUTTONRSTn/MCU_JTAG_TCK/GPIO0_B4_u, 149 HDMI_TX_CLKP, 150 I2C2_SCL_M0/SPI0_CLK_M0/PCIE20_WAKEn_M0/PWM1_M1/GPIO0_B5_u, 151 HDMI_TX_D0P, 152 I2C2_SDA_M0/SPI0_MOSI_M0/PCIE20_PERSTn_M0/PWM2_M1/GPIO0_B6_u, 153 HDMI_TX_D0N, 154 I2C3_SDA_M0/UART3_RX_M0/CAN1_RX_M0/AUDIOPWM_LOUT_P/ACODEC_ADC_DATA/GPIO1_A0_u, 155 HDMI_TX_D1P, 156 I2C3_SCL_M0/UART3_TX_M0/CAN1_TX_M0/AUDIOPWM_LOUT_N/ACODEC_ADC_CLK/GPIO1_A1_u, 157 HDMI_TX_D1N, 158 GND12, 159 HDMI_TX_D2P, 160 PCIE30_RX1N, 161 HDMI_TX_D2N, 162 PCIE30_RX1P, 163 GND13, 164 PCIE30_RX0N, 165 USB3_HOST1_DP, 166 PCIE30_RX0P, 167 USB3_HOST1_DM, 168 PCIE30_TX1N, 169 USB3_HOST1_SSTXN/SATA1_TXN/QSGMII_TXN_M0, 170 PCIE30_TX1P, 171 USB3_HOST1_SSTXP/SATA1_TXP/QSGMII_TXP_M0, 172 PCIE30_TX0N, 173 USB3_HOST1_SSRXN/SATA1_RXN/QSGMII_RXN_M0, 174 PCIE30_TX0P, 175 USB3_HOST1_SSRXP/SATA1_RXP/QSGMII_RXP_M0, 176 PCIE30_REFCLKN_IN, 177 GND14, 178 PCIE30_REFCLKP_IN, 179 USB3_OTG0_SSTXN/SATA0_TXN, 180 GND15, 181 USB3_OTG0_SSTXP/SATA0_TXP, 182 PCIE20_REFCLKP, 183 USB3_OTG0_SSRXN/SATA0_RXN, 184 PCIE20_REFCLKN, 185 USB3_OTG0_SSRXP/SATA0_RXP, 186 PCIE20_RXP/SATA2_RXP/QSGMII_RXP_M1, 187 USB3_OTG0_DP, 188 PCIE20_RXN/SATA2_RXN/QSGMII_RXN_M1, 189 USB3_OTG0_DM, 190 PCIE20_TXP/SATA2_TXP/QSGMII_TXP_M1, 191 USB3_OTG0_VBUSDET, 192 PCIE20_TXN/SATA2_TXN/QSGMII_TXN_M1, 193 USB3_OTG0_ID, 194 GND16, 195 GND17, 196 SDMMC0_D0/UART2_TX_M1/UART6_TX_M1/PWM8_M1/GPIO1_D5_u, 197 EDP_TX_AUXN, 198 SDMMC0_D1/UART2_RX_M1/UART6_RX_M1/PWM9_M1/GPIO1_D6_u, 199 EDP_TX_AUXP, 200 SDMMC0_D2/ARMJTAG_TCK/UART5_CTSn_M0/GPIO1_D7_u, 201 EDP_TX_D3N, 202 SDMMC0_D3/ARMJTAG_TMS/UART5_RTSn_M0/GPIO2_A0_u, 203 EDP_TX_D3P, 204 SDMMC0_CMD/PWM10_M1/UART5_RX_M0/CAN0_TX_M1/GPIO2_A1_u, 205 EDP_TX_D2N, 206 SDMMC0_CLK/TEST_CLKOUT/UART5_TX_M0/CAN0_RX_M1/GPIO2_A2_d, 207 EDP_TX_D2P, 208 SDMMC0_DET/SATA_CP_DET/PCIE30X1_CLKREQn_M0/GPIO0_A4_u, 209 EDP_TX_D1N, 210 VCC3V3_SD_OUT, 211 EDP_TX_D1P, 212 SDMMC0_PWREN/SATA_MP_SWITCH/PCIE20_CLKREQn_M0/GPIO0_A5_d, 213 EDP_TX_D0N, 214 GND18, 215 EDP_TX_D0P, 216 GMAC0_TXD0/UART1_RX_M0/GPIO2_B3_u, 217 GND19, 218 GMAC0_TXD1/UART1_TX_M0/GPIO2_B4_u, 219 SDMMC1_D0/GMAC0_RXD2/UART6_RX_M0/GPIO2_A3_u, 220 GMAC0_TXEN/UART1_RTSn_M0/SPI1_CLK_M0/GPIO2_B5_u, 221 SDMMC1_D1/GMAC0_RXD3/UART6_TX_M0/GPIO2_A4_u, 222 GMAC0_RXD0/UART1_CTSn_M0/SPI1_MISO_M0/GPIO2_B6_u, 223 SDMMC1_D2/GMAC0_RXCLK/UART7_RX_M0/GPIO2_A5_u, 224 I2S2_SCLK_RX_M0/GMAC0_RXD1/UART6_RTSn_M0/SPI1_MOSI_M0/GPIO2_B7_d, 225 SDMMC1_D3/GMAC0_TXD2/UART7_TX_M0/GPIO2_A6_u, 226 I2S2_LRCK_RX_M0/GMAC0_RXDV_CRS/UART6_CTSn_M0/SPI1_CS0_M0/GPIO2_C0_d, 227 SDMMC1_CMD/GMAC0_TXD3/UART9_RX_M0/GPIO2_A7_u, 228 I2S2_MCLK_M0/ETH0_REFCLKO_25M/UART7_RTSn_M0/SPI2_CLK_M0/GPIO2_C1_d, 229 SDMMC1_CLK/GMAC0_TXCLK/UART9_TX_M0/GPIO2_B0_d, 230 I2S2_SCLK_TX_M0/GMAC0_MCLKINOUT/UART7_CTSn_M0/SPI2_MISO_M0/GPIO2_C2_d, 231 SDMMC1_PWREN/I2C4_SDA_M1/UART8_RTSn_M0/CAN2_RX_M1/GPIO2_B1_d, 232 I2S2_LRCK_TX_M0/GMAC0_MDC/UART9_RTSn_M0/SPI2_MOSI_M0/GPIO2_C3_d, 233 SDMMC1_DET/I2C4_SCL_M1/UART8_CTSn_M0/CAN2_TX_M1/GPIO2_B2_u, 234 I2S2_SDO_M0/GMAC0_MDIO/UART9_CTSn_M0/SPI2_CS0_M0/GPIO2_C4_d, 235 SYS_RESETn, 236 I2S2_SDI_M0/GMAC0_RXER/UART8_TX_M0/SPI2_CS1_M0/GPIO2_C5_d, 237 VCC_1V8_OUT, 238 CLK32K_OUT1/UART8_RX_M0/SPI1_CS1_M0/GPIO2_C6_d, 239 BATDIV, 240 GND20, 241 SNSP, 242 HPL_OUT, 243 SNSN, 244 HP_SNS, 245 VCC_3V3_OUT, 246 HPR_OUT, 247 RK809-CLK32K, 248 MIC1_INP, 249 EXT_EN, 250 MIC1_INN, 251 RK809_PWRON, 252 RK809_VDC, 253 VCC5V0_SYS1, 254 GND21, 255 VCC5V0_SYS2, 256 GND22, 257 VCC5V0_SYS3, 258 GND23, 259 VCC5V0_SYS4, 260 GND24

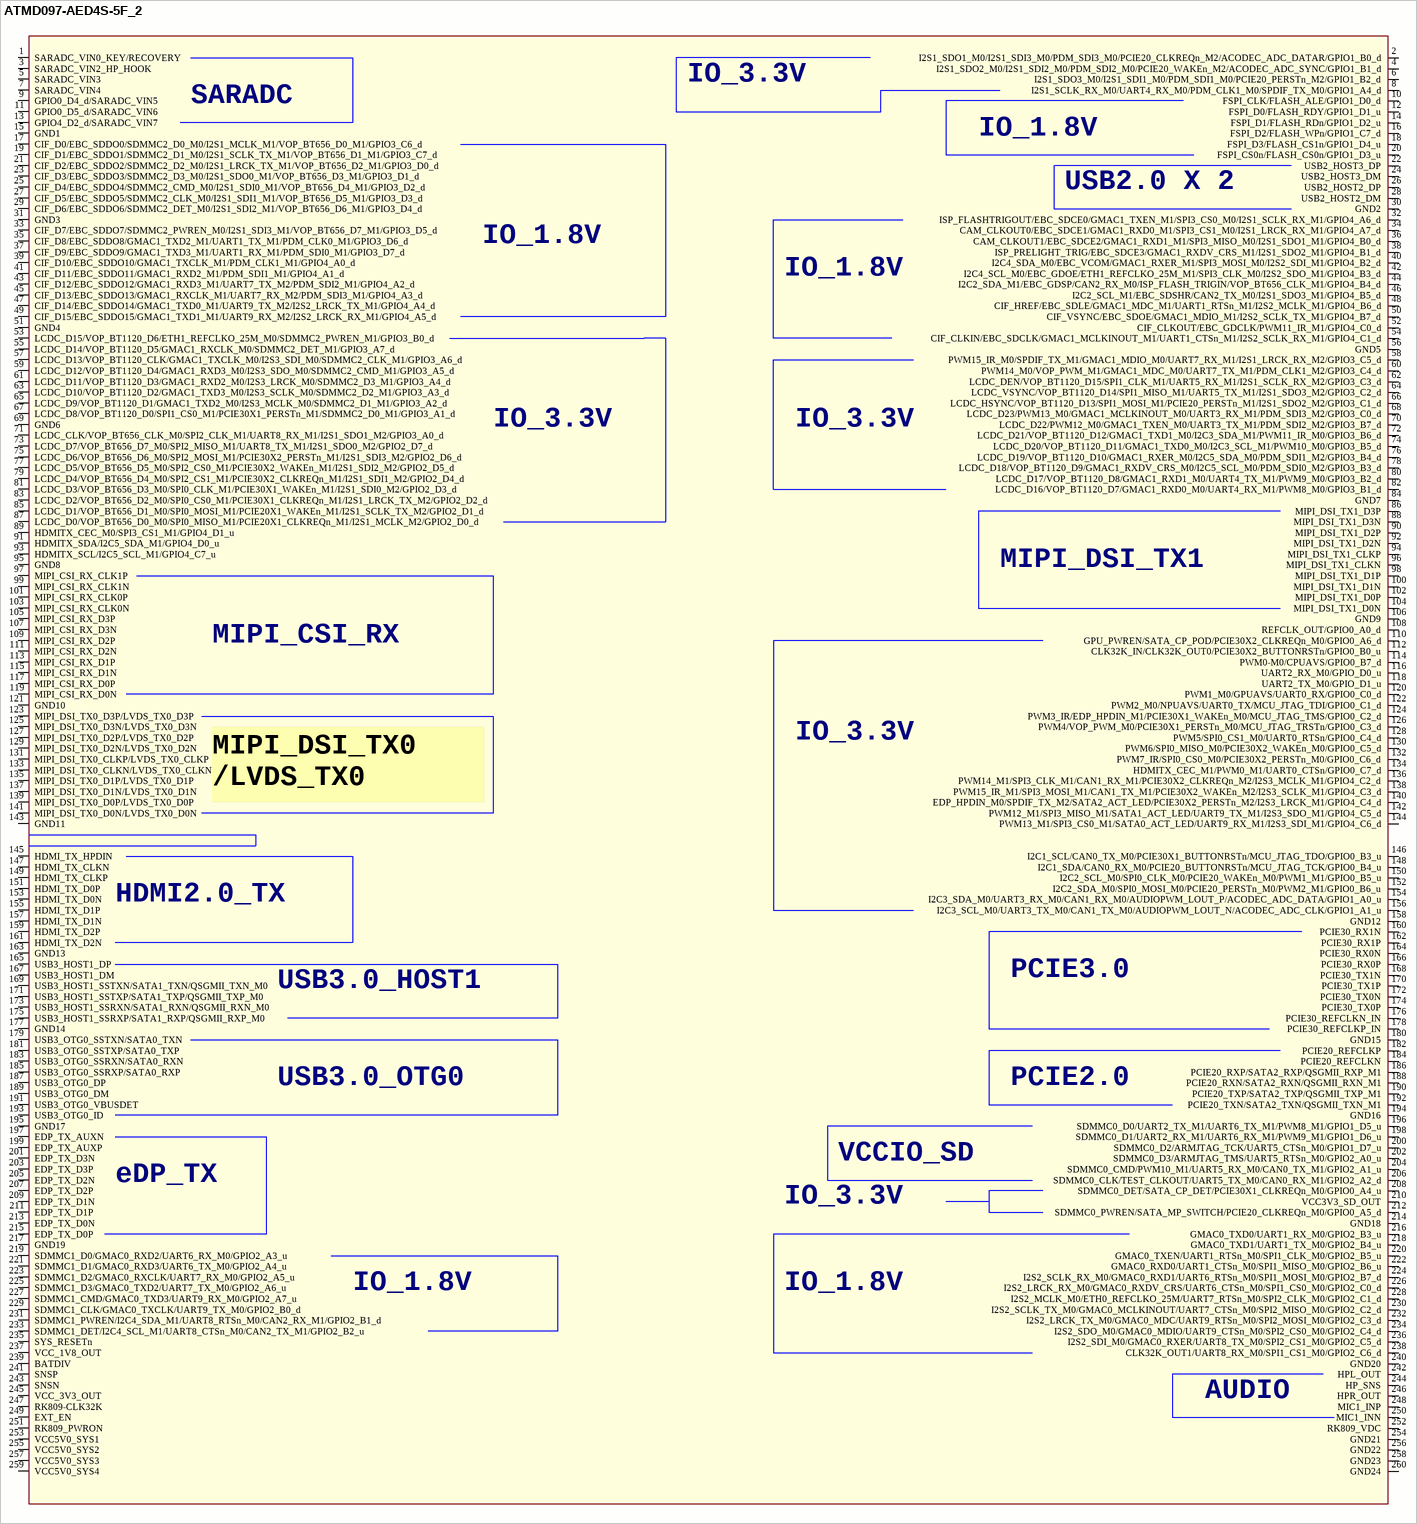
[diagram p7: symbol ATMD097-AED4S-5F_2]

## ATMD097-AED4S-5F_2
designator J?
Altium-Right: 1260; Altium-Bottom: 1360
pins: 1 SARADC_VIN0_KEY/RECOVERY, 2 I2S1_SDO1_M0/I2S1_SDI3_M0/PDM_SDI3_M0/PCIE20_CLKREQn_M2/ACODEC_ADC_DATAR/GPIO1_B0_d, 3 SARADC_VIN2_HP_HOOK, 4 I2S1_SDO2_M0/I2S1_SDI2_M0/PDM_SDI2_M0/PCIE20_WAKEn_M2/ACODEC_ADC_SYNC/GPIO1_B1_d, 5 SARADC_VIN3, 6 I2S1_SDO3_M0/I2S1_SDI1_M0/PDM_SDI1_M0/PCIE20_PERSTn_M2/GPIO1_B2_d, 7 SARADC_VIN4, 8 I2S1_SCLK_RX_M0/UART4_RX_M0/PDM_CLK1_M0/SPDIF_TX_M0/GPIO1_A4_d, 9 GPIO0_D4_d/SARADC_VIN5, 10 FSPI_CLK/FLASH_ALE/GPIO1_D0_d, 11 GPIO0_D5_d/SARADC_VIN6, 12 FSPI_D0/FLASH_RDY/GPIO1_D1_u, 13 GPIO4_D2_d/SARADC_VIN7, 14 FSPI_D1/FLASH_RDn/GPIO1_D2_u, 15 GND1, 16 FSPI_D2/FLASH_WPn/GPIO1_C7_d, 17 CIF_D0/EBC_SDDO0/SDMMC2_D0_M0/I2S1_MCLK_M1/VOP_BT656_D0_M1/GPIO3_C6_d, 18 FSPI_D3/FLASH_CS1n/GPIO1_D4_u, 19 CIF_D1/EBC_SDDO1/SDMMC2_D1_M0/I2S1_SCLK_TX_M1/VOP_BT656_D1_M1/GPIO3_C7_d, 20 FSPI_CS0n/FLASH_CS0n/GPIO1_D3_u, 21 CIF_D2/EBC_SDDO2/SDMMC2_D2_M0/I2S1_LRCK_TX_M1/VOP_BT656_D2_M1/GPIO3_D0_d, 22 USB2_HOST3_DP, 23 CIF_D3/EBC_SDDO3/SDMMC2_D3_M0/I2S1_SDO0_M1/VOP_BT656_D3_M1/GPIO3_D1_d, 24 USB2_HOST3_DM, 25 CIF_D4/EBC_SDDO4/SDMMC2_CMD_M0/I2S1_SDI0_M1/VOP_BT656_D4_M1/GPIO3_D2_d, 26 USB2_HOST2_DP, 27 CIF_D5/EBC_SDDO5/SDMMC2_CLK_M0/I2S1_SDI1_M1/VOP_BT656_D5_M1/GPIO3_D3_d, 28 USB2_HOST2_DM, 29 CIF_D6/EBC_SDDO6/SDMMC2_DET_M0/I2S1_SDI2_M1/VOP_BT656_D6_M1/GPIO3_D4_d, 30 GND2, 31 GND3, 32 ISP_FLASHTRIGOUT/EBC_SDCE0/GMAC1_TXEN_M1/SPI3_CS0_M0/I2S1_SCLK_RX_M1/GPIO4_A6_d, 33 CIF_D7/EBC_SDDO7/SDMMC2_PWREN_M0/I2S1_SDI3_M1/VOP_BT656_D7_M1/GPIO3_D5_d, 34 CAM_CLKOUT0/EBC_SDCE1/GMAC1_RXD0_M1/SPI3_CS1_M0/I2S1_LRCK_RX_M1/GPIO4_A7_d, 35 CIF_D8/EBC_SDDO8/GMAC1_TXD2_M1/UART1_TX_M1/PDM_CLK0_M1/GPIO3_D6_d, 36 CAM_CLKOUT1/EBC_SDCE2/GMAC1_RXD1_M1/SPI3_MISO_M0/I2S1_SDO1_M1/GPIO4_B0_d, 37 CIF_D9/EBC_SDDO9/GMAC1_TXD3_M1/UART1_RX_M1/PDM_SDI0_M1/GPIO3_D7_d, 38 ISP_PRELIGHT_TRIG/EBC_SDCE3/GMAC1_RXDV_CRS_M1/I2S1_SDO2_M1/GPIO4_B1_d, 39 CIF_D10/EBC_SDDO10/GMAC1_TXCLK_M1/PDM_CLK1_M1/GPIO4_A0_d, 40 I2C4_SDA_M0/EBC_VCOM/GMAC1_RXER_M1/SPI3_MOSI_M0/I2S2_SDI_M1/GPIO4_B2_d, 41 CIF_D11/EBC_SDDO11/GMAC1_RXD2_M1/PDM_SDI1_M1/GPIO4_A1_d, 42 I2C4_SCL_M0/EBC_GDOE/ETH1_REFCLKO_25M_M1/SPI3_CLK_M0/I2S2_SDO_M1/GPIO4_B3_d, 43 CIF_D12/EBC_SDDO12/GMAC1_RXD3_M1/UART7_TX_M2/PDM_SDI2_M1/GPIO4_A2_d, 44 I2C2_SDA_M1/EBC_GDSP/CAN2_RX_M0/ISP_FLASH_TRIGIN/VOP_BT656_CLK_M1/GPIO4_B4_d, 45 CIF_D13/EBC_SDDO13/GMAC1_RXCLK_M1/UART7_RX_M2/PDM_SDI3_M1/GPIO4_A3_d, 46 I2C2_SCL_M1/EBC_SDSHR/CAN2_TX_M0/I2S1_SDO3_M1/GPIO4_B5_d, 47 CIF_D14/EBC_SDDO14/GMAC1_TXD0_M1/UART9_TX_M2/I2S2_LRCK_TX_M1/GPIO4_A4_d, 48 CIF_HREF/EBC_SDLE/GMAC1_MDC_M1/UART1_RTSn_M1/I2S2_MCLK_M1/GPIO4_B6_d, 49 CIF_D15/EBC_SDDO15/GMAC1_TXD1_M1/UART9_RX_M2/I2S2_LRCK_RX_M1/GPIO4_A5_d, 50 CIF_VSYNC/EBC_SDOE/GMAC1_MDIO_M1/I2S2_SCLK_TX_M1/GPIO4_B7_d, 51 GND4, 52 CIF_CLKOUT/EBC_GDCLK/PWM11_IR_M1/GPIO4_C0_d, 53 LCDC_D15/VOP_BT1120_D6/ETH1_REFCLKO_25M_M0/SDMMC2_PWREN_M1/GPIO3_B0_d, 54 CIF_CLKIN/EBC_SDCLK/GMAC1_MCLKINOUT_M1/UART1_CTSn_M1/I2S2_SCLK_RX_M1/GPIO4_C1_d, 55 LCDC_D14/VOP_BT1120_D5/GMAC1_RXCLK_M0/SDMMC2_DET_M1/GPIO3_A7_d, 56 GND5, 57 LCDC_D13/VOP_BT1120_CLK/GMAC1_TXCLK_M0/I2S3_SDI_M0/SDMMC2_CLK_M1/GPIO3_A6_d, 58 PWM15_IR_M0/SPDIF_TX_M1/GMAC1_MDIO_M0/UART7_RX_M1/I2S1_LRCK_RX_M2/GPIO3_C5_d, 59 LCDC_D12/VOP_BT1120_D4/GMAC1_RXD3_M0/I2S3_SDO_M0/SDMMC2_CMD_M1/GPIO3_A5_d, 60 PWM14_M0/VOP_PWM_M1/GMAC1_MDC_M0/UART7_TX_M1/PDM_CLK1_M2/GPIO3_C4_d, 61 LCDC_D11/VOP_BT1120_D3/GMAC1_RXD2_M0/I2S3_LRCK_M0/SDMMC2_D3_M1/GPIO3_A4_d, 62 LCDC_DEN/VOP_BT1120_D15/SPI1_CLK_M1/UART5_RX_M1/I2S1_SCLK_RX_M2/GPIO3_C3_d, 63 LCDC_D10/VOP_BT1120_D2/GMAC1_TXD3_M0/I2S3_SCLK_M0/SDMMC2_D2_M1/GPIO3_A3_d, 64 LCDC_VSYNC/VOP_BT1120_D14/SPI1_MISO_M1/UART5_TX_M1/I2S1_SDO3_M2/GPIO3_C2_d, 65 LCDC_D9/VOP_BT1120_D1/GMAC1_TXD2_M0/I2S3_MCLK_M0/SDMMC2_D1_M1/GPIO3_A2_d, 66 LCDC_HSYNC/VOP_BT1120_D13/SPI1_MOSI_M1/PCIE20_PERSTn_M1/I2S1_SDO2_M2/GPIO3_C1_d, 67 LCDC_D8/VOP_BT1120_D0/SPI1_CS0_M1/PCIE30X1_PERSTn_M1/SDMMC2_D0_M1/GPIO3_A1_d, 68 LCDC_D23/PWM13_M0/GMAC1_MCLKINOUT_M0/UART3_RX_M1/PDM_SDI3_M2/GPIO3_C0_d, 69 GND6, 70 LCDC_D22/PWM12_M0/GMAC1_TXEN_M0/UART3_TX_M1/PDM_SDI2_M2/GPIO3_B7_d, 71 LCDC_CLK/VOP_BT656_CLK_M0/SPI2_CLK_M1/UART8_RX_M1/I2S1_SDO1_M2/GPIO3_A0_d, 72 LCDC_D21/VOP_BT1120_D12/GMAC1_TXD1_M0/I2C3_SDA_M1/PWM11_IR_M0/GPIO3_B6_d, 73 LCDC_D7/VOP_BT656_D7_M0/SPI2_MISO_M1/UART8_TX_M1/I2S1_SDO0_M2/GPIO2_D7_d, 74 LCDC_D20/VOP_BT1120_D11/GMAC1_TXD0_M0/I2C3_SCL_M1/PWM10_M0/GPIO3_B5_d, 75 LCDC_D6/VOP_BT656_D6_M0/SPI2_MOSI_M1/PCIE30X2_PERSTn_M1/I2S1_SDI3_M2/GPIO2_D6_d, 76 LCDC_D19/VOP_BT1120_D10/GMAC1_RXER_M0/I2C5_SDA_M0/PDM_SDI1_M2/GPIO3_B4_d, 77 LCDC_D5/VOP_BT656_D5_M0/SPI2_CS0_M1/PCIE30X2_WAKEn_M1/I2S1_SDI2_M2/GPIO2_D5_d, 78 LCDC_D18/VOP_BT1120_D9/GMAC1_RXDV_CRS_M0/I2C5_SCL_M0/PDM_SDI0_M2/GPIO3_B3_d, 79 LCDC_D4/VOP_BT656_D4_M0/SPI2_CS1_M1/PCIE30X2_CLKREQn_M1/I2S1_SDI1_M2/GPIO2_D4_d, 80 LCDC_D17/VOP_BT1120_D8/GMAC1_RXD1_M0/UART4_TX_M1/PWM9_M0/GPIO3_B2_d, 81 LCDC_D3/VOP_BT656_D3_M0/SPI0_CLK_M1/PCIE30X1_WAKEn_M1/I2S1_SDI0_M2/GPIO2_D3_d, 82 LCDC_D16/VOP_BT1120_D7/GMAC1_RXD0_M0/UART4_RX_M1/PWM8_M0/GPIO3_B1_d, 83 LCDC_D2/VOP_BT656_D2_M0/SPI0_CS0_M1/PCIE30X1_CLKREQn_M1/I2S1_LRCK_TX_M2/GPIO2_D2_d, 84 GND7, 85 LCDC_D1/VOP_BT656_D1_M0/SPI0_MOSI_M1/PCIE20X1_WAKEn_M1/I2S1_SCLK_TX_M2/GPIO2_D1_d, 86 MIPI_DSI_TX1_D3P, 87 LCDC_D0/VOP_BT656_D0_M0/SPI0_MISO_M1/PCIE20X1_CLKREQn_M1/I2S1_MCLK_M2/GPIO2_D0_d, 88 MIPI_DSI_TX1_D3N, 89 HDMITX_CEC_M0/SPI3_CS1_M1/GPIO4_D1_u, 90 MIPI_DSI_TX1_D2P, 91 HDMITX_SDA/I2C5_SDA_M1/GPIO4_D0_u, 92 MIPI_DSI_TX1_D2N, 93 HDMITX_SCL/I2C5_SCL_M1/GPIO4_C7_u, 94 MIPI_DSI_TX1_CLKP, 95 GND8, 96 MIPI_DSI_TX1_CLKN, 97 MIPI_CSI_RX_CLK1P, 98 MIPI_DSI_TX1_D1P, 99 MIPI_CSI_RX_CLK1N, 100 MIPI_DSI_TX1_D1N, 101 MIPI_CSI_RX_CLK0P, 102 MIPI_DSI_TX1_D0P, 103 MIPI_CSI_RX_CLK0N, 104 MIPI_DSI_TX1_D0N, 105 MIPI_CSI_RX_D3P, 106 GND9, 107 MIPI_CSI_RX_D3N, 108 REFCLK_OUT/GPIO0_A0_d, 109 MIPI_CSI_RX_D2P, 110 GPU_PWREN/SATA_CP_POD/PCIE30X2_CLKREQn_M0/GPIO0_A6_d, 111 MIPI_CSI_RX_D2N, 112 CLK32K_IN/CLK32K_OUT0/PCIE30X2_BUTTONRSTn/GPIO0_B0_u, 113 MIPI_CSI_RX_D1P, 114 PWM0-M0/CPUAVS/GPIO0_B7_d, 115 MIPI_CSI_RX_D1N, 116 UART2_RX_M0/GPIO_D0_u, 117 MIPI_CSI_RX_D0P, 118 UART2_TX_M0/GPIO_D1_u, 119 MIPI_CSI_RX_D0N, 120 PWM1_M0/GPUAVS/UART0_RX/GPIO0_C0_d, 121 GND10, 122 PWM2_M0/NPUAVS/UART0_TX/MCU_JTAG_TDI/GPIO0_C1_d, 123 MIPI_DSI_TX0_D3P/LVDS_TX0_D3P, 124 PWM3_IR/EDP_HPDIN_M1/PCIE30X1_WAKEn_M0/MCU_JTAG_TMS/GPIO0_C2_d, 125 MIPI_DSI_TX0_D3N/LVDS_TX0_D3N, 126 PWM4/VOP_PWM_M0/PCIE30X1_PERSTn_M0/MCU_JTAG_TRSTn/GPIO0_C3_d, 127 MIPI_DSI_TX0_D2P/LVDS_TX0_D2P, 128 PWM5/SPI0_CS1_M0/UART0_RTSn/GPIO0_C4_d, 129 MIPI_DSI_TX0_D2N/LVDS_TX0_D2N, 130 PWM6/SPI0_MISO_M0/PCIE30X2_WAKEn_M0/GPIO0_C5_d, 131 MIPI_DSI_TX0_CLKP/LVDS_TX0_CLKP, 132 PWM7_IR/SPI0_CS0_M0/PCIE30X2_PERSTn_M0/GPIO0_C6_d, 133 MIPI_DSI_TX0_CLKN/LVDS_TX0_CLKN, 134 HDMITX_CEC_M1/PWM0_M1/UART0_CTSn/GPIO0_C7_d, 135 MIPI_DSI_TX0_D1P/LVDS_TX0_D1P, 136 PWM14_M1/SPI3_CLK_M1/CAN1_RX_M1/PCIE30X2_CLKREQn_M2/I2S3_MCLK_M1/GPIO4_C2_d, 137 MIPI_DSI_TX0_D1N/LVDS_TX0_D1N, 138 PWM15_IR_M1/SPI3_MOSI_M1/CAN1_TX_M1/PCIE30X2_WAKEn_M2/I2S3_SCLK_M1/GPIO4_C3_d, 139 MIPI_DSI_TX0_D0P/LVDS_TX0_D0P, 140 EDP_HPDIN_M0/SPDIF_TX_M2/SATA2_ACT_LED/PCIE30X2_PERSTn_M2/I2S3_LRCK_M1/GPIO4_C4_d, 141 MIPI_DSI_TX0_D0N/LVDS_TX0_D0N, 142 PWM12_M1/SPI3_MISO_M1/SATA1_ACT_LED/UART9_TX_M1/I2S3_SDO_M1/GPIO4_C5_d, 143 GND11, 144 PWM13_M1/SPI3_CS0_M1/SATA0_ACT_LED/UART9_RX_M1/I2S3_SDI_M1/GPIO4_C6_d, 145 HDMI_TX_HPDIN, 146 I2C1_SCL/CAN0_TX_M0/PCIE30X1_BUTTONRSTn/MCU_JTAG_TDO/GPIO0_B3_u, 147 HDMI_TX_CLKN, 148 I2C1_SDA/CAN0_RX_M0/PCIE20_BUTTONRSTn/MCU_JTAG_TCK/GPIO0_B4_u, 149 HDMI_TX_CLKP, 150 I2C2_SCL_M0/SPI0_CLK_M0/PCIE20_WAKEn_M0/PWM1_M1/GPIO0_B5_u, 151 HDMI_TX_D0P, 152 I2C2_SDA_M0/SPI0_MOSI_M0/PCIE20_PERSTn_M0/PWM2_M1/GPIO0_B6_u, 153 HDMI_TX_D0N, 154 I2C3_SDA_M0/UART3_RX_M0/CAN1_RX_M0/AUDIOPWM_LOUT_P/ACODEC_ADC_DATA/GPIO1_A0_u, 155 HDMI_TX_D1P, 156 I2C3_SCL_M0/UART3_TX_M0/CAN1_TX_M0/AUDIOPWM_LOUT_N/ACODEC_ADC_CLK/GPIO1_A1_u, 157 HDMI_TX_D1N, 158 GND12, 159 HDMI_TX_D2P, 160 PCIE30_RX1N, 161 HDMI_TX_D2N, 162 PCIE30_RX1P, 163 GND13, 164 PCIE30_RX0N, 165 USB3_HOST1_DP, 166 PCIE30_RX0P, 167 USB3_HOST1_DM, 168 PCIE30_TX1N, 169 USB3_HOST1_SSTXN/SATA1_TXN/QSGMII_TXN_M0, 170 PCIE30_TX1P, 171 USB3_HOST1_SSTXP/SATA1_TXP/QSGMII_TXP_M0, 172 PCIE30_TX0N, 173 USB3_HOST1_SSRXN/SATA1_RXN/QSGMII_RXN_M0, 174 PCIE30_TX0P, 175 USB3_HOST1_SSRXP/SATA1_RXP/QSGMII_RXP_M0, 176 PCIE30_REFCLKN_IN, 177 GND14, 178 PCIE30_REFCLKP_IN, 179 USB3_OTG0_SSTXN/SATA0_TXN, 180 GND15, 181 USB3_OTG0_SSTXP/SATA0_TXP, 182 PCIE20_REFCLKP, 183 USB3_OTG0_SSRXN/SATA0_RXN, 184 PCIE20_REFCLKN, 185 USB3_OTG0_SSRXP/SATA0_RXP, 186 PCIE20_RXP/SATA2_RXP/QSGMII_RXP_M1, 187 USB3_OTG0_DP, 188 PCIE20_RXN/SATA2_RXN/QSGMII_RXN_M1, 189 USB3_OTG0_DM, 190 PCIE20_TXP/SATA2_TXP/QSGMII_TXP_M1, 191 USB3_OTG0_VBUSDET, 192 PCIE20_TXN/SATA2_TXN/QSGMII_TXN_M1, 193 USB3_OTG0_ID, 194 GND16, 195 GND17, 196 SDMMC0_D0/UART2_TX_M1/UART6_TX_M1/PWM8_M1/GPIO1_D5_u, 197 EDP_TX_AUXN, 198 SDMMC0_D1/UART2_RX_M1/UART6_RX_M1/PWM9_M1/GPIO1_D6_u, 199 EDP_TX_AUXP, 200 SDMMC0_D2/ARMJTAG_TCK/UART5_CTSn_M0/GPIO1_D7_u, 201 EDP_TX_D3N, 202 SDMMC0_D3/ARMJTAG_TMS/UART5_RTSn_M0/GPIO2_A0_u, 203 EDP_TX_D3P, 204 SDMMC0_CMD/PWM10_M1/UART5_RX_M0/CAN0_TX_M1/GPIO2_A1_u, 205 EDP_TX_D2N, 206 SDMMC0_CLK/TEST_CLKOUT/UART5_TX_M0/CAN0_RX_M1/GPIO2_A2_d, 207 EDP_TX_D2P, 208 SDMMC0_DET/SATA_CP_DET/PCIE30X1_CLKREQn_M0/GPIO0_A4_u, 209 EDP_TX_D1N, 210 VCC3V3_SD_OUT, 211 EDP_TX_D1P, 212 SDMMC0_PWREN/SATA_MP_SWITCH/PCIE20_CLKREQn_M0/GPIO0_A5_d, 213 EDP_TX_D0N, 214 GND18, 215 EDP_TX_D0P, 216 GMAC0_TXD0/UART1_RX_M0/GPIO2_B3_u, 217 GND19, 218 GMAC0_TXD1/UART1_TX_M0/GPIO2_B4_u, 219 SDMMC1_D0/GMAC0_RXD2/UART6_RX_M0/GPIO2_A3_u, 220 GMAC0_TXEN/UART1_RTSn_M0/SPI1_CLK_M0/GPIO2_B5_u, 221 SDMMC1_D1/GMAC0_RXD3/UART6_TX_M0/GPIO2_A4_u, 222 GMAC0_RXD0/UART1_CTSn_M0/SPI1_MISO_M0/GPIO2_B6_u, 223 SDMMC1_D2/GMAC0_RXCLK/UART7_RX_M0/GPIO2_A5_u, 224 I2S2_SCLK_RX_M0/GMAC0_RXD1/UART6_RTSn_M0/SPI1_MOSI_M0/GPIO2_B7_d, 225 SDMMC1_D3/GMAC0_TXD2/UART7_TX_M0/GPIO2_A6_u, 226 I2S2_LRCK_RX_M0/GMAC0_RXDV_CRS/UART6_CTSn_M0/SPI1_CS0_M0/GPIO2_C0_d, 227 SDMMC1_CMD/GMAC0_TXD3/UART9_RX_M0/GPIO2_A7_u, 228 I2S2_MCLK_M0/ETH0_REFCLKO_25M/UART7_RTSn_M0/SPI2_CLK_M0/GPIO2_C1_d, 229 SDMMC1_CLK/GMAC0_TXCLK/UART9_TX_M0/GPIO2_B0_d, 230 I2S2_SCLK_TX_M0/GMAC0_MCLKINOUT/UART7_CTSn_M0/SPI2_MISO_M0/GPIO2_C2_d, 231 SDMMC1_PWREN/I2C4_SDA_M1/UART8_RTSn_M0/CAN2_RX_M1/GPIO2_B1_d, 232 I2S2_LRCK_TX_M0/GMAC0_MDC/UART9_RTSn_M0/SPI2_MOSI_M0/GPIO2_C3_d, 233 SDMMC1_DET/I2C4_SCL_M1/UART8_CTSn_M0/CAN2_TX_M1/GPIO2_B2_u, 234 I2S2_SDO_M0/GMAC0_MDIO/UART9_CTSn_M0/SPI2_CS0_M0/GPIO2_C4_d, 235 SYS_RESETn, 236 I2S2_SDI_M0/GMAC0_RXER/UART8_TX_M0/SPI2_CS1_M0/GPIO2_C5_d, 237 VCC_1V8_OUT, 238 CLK32K_OUT1/UART8_RX_M0/SPI1_CS1_M0/GPIO2_C6_d, 239 BATDIV, 240 GND20, 241 SNSP, 242 HPL_OUT, 243 SNSN, 244 HP_SNS, 245 VCC_3V3_OUT, 246 HPR_OUT, 247 RK809-CLK32K, 248 MIC1_INP, 249 EXT_EN, 250 MIC1_INN, 251 RK809_PWRON, 252 RK809_VDC, 253 VCC5V0_SYS1, 254 GND21, 255 VCC5V0_SYS2, 256 GND22, 257 VCC5V0_SYS3, 258 GND23, 259 VCC5V0_SYS4, 260 GND24

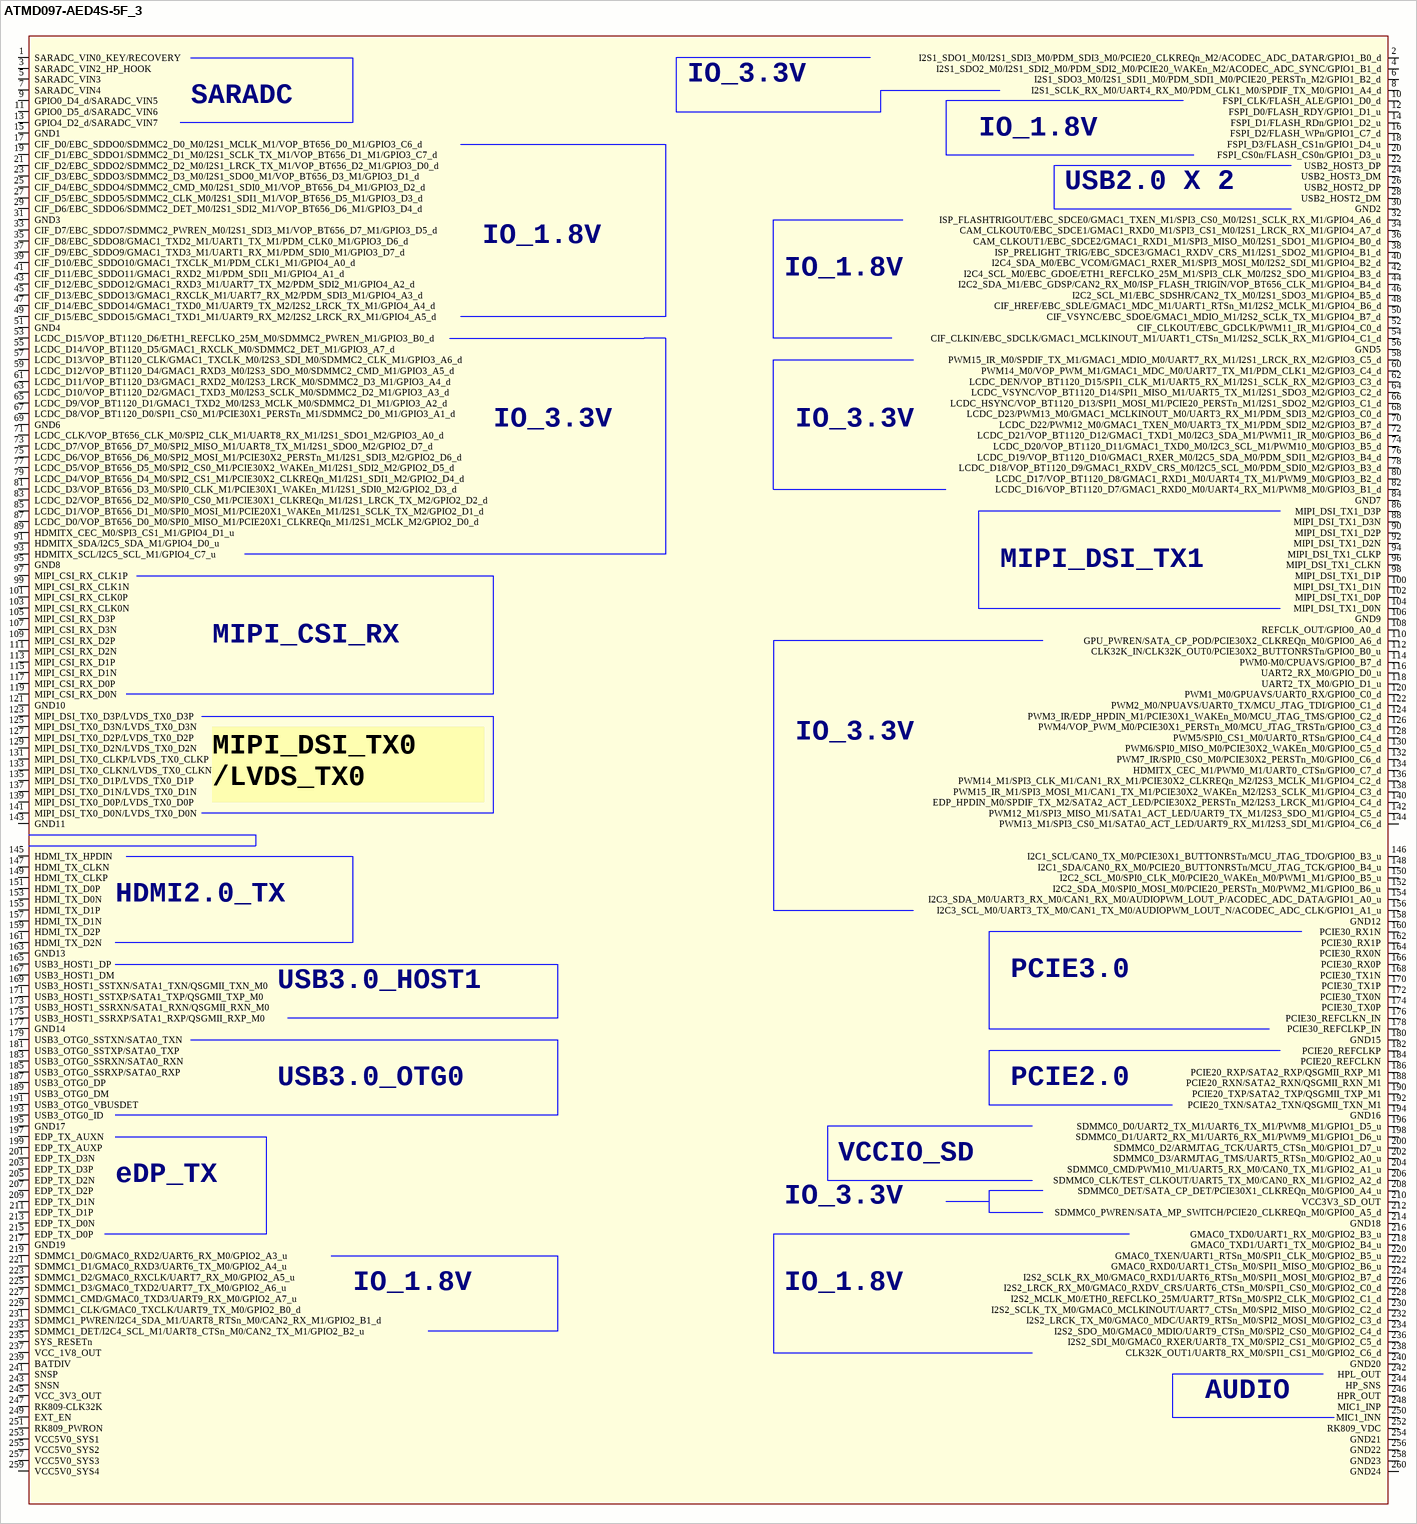
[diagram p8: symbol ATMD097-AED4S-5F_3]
